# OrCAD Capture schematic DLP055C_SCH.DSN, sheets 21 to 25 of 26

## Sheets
21 P13 - DLPC Core Pwr: size A3
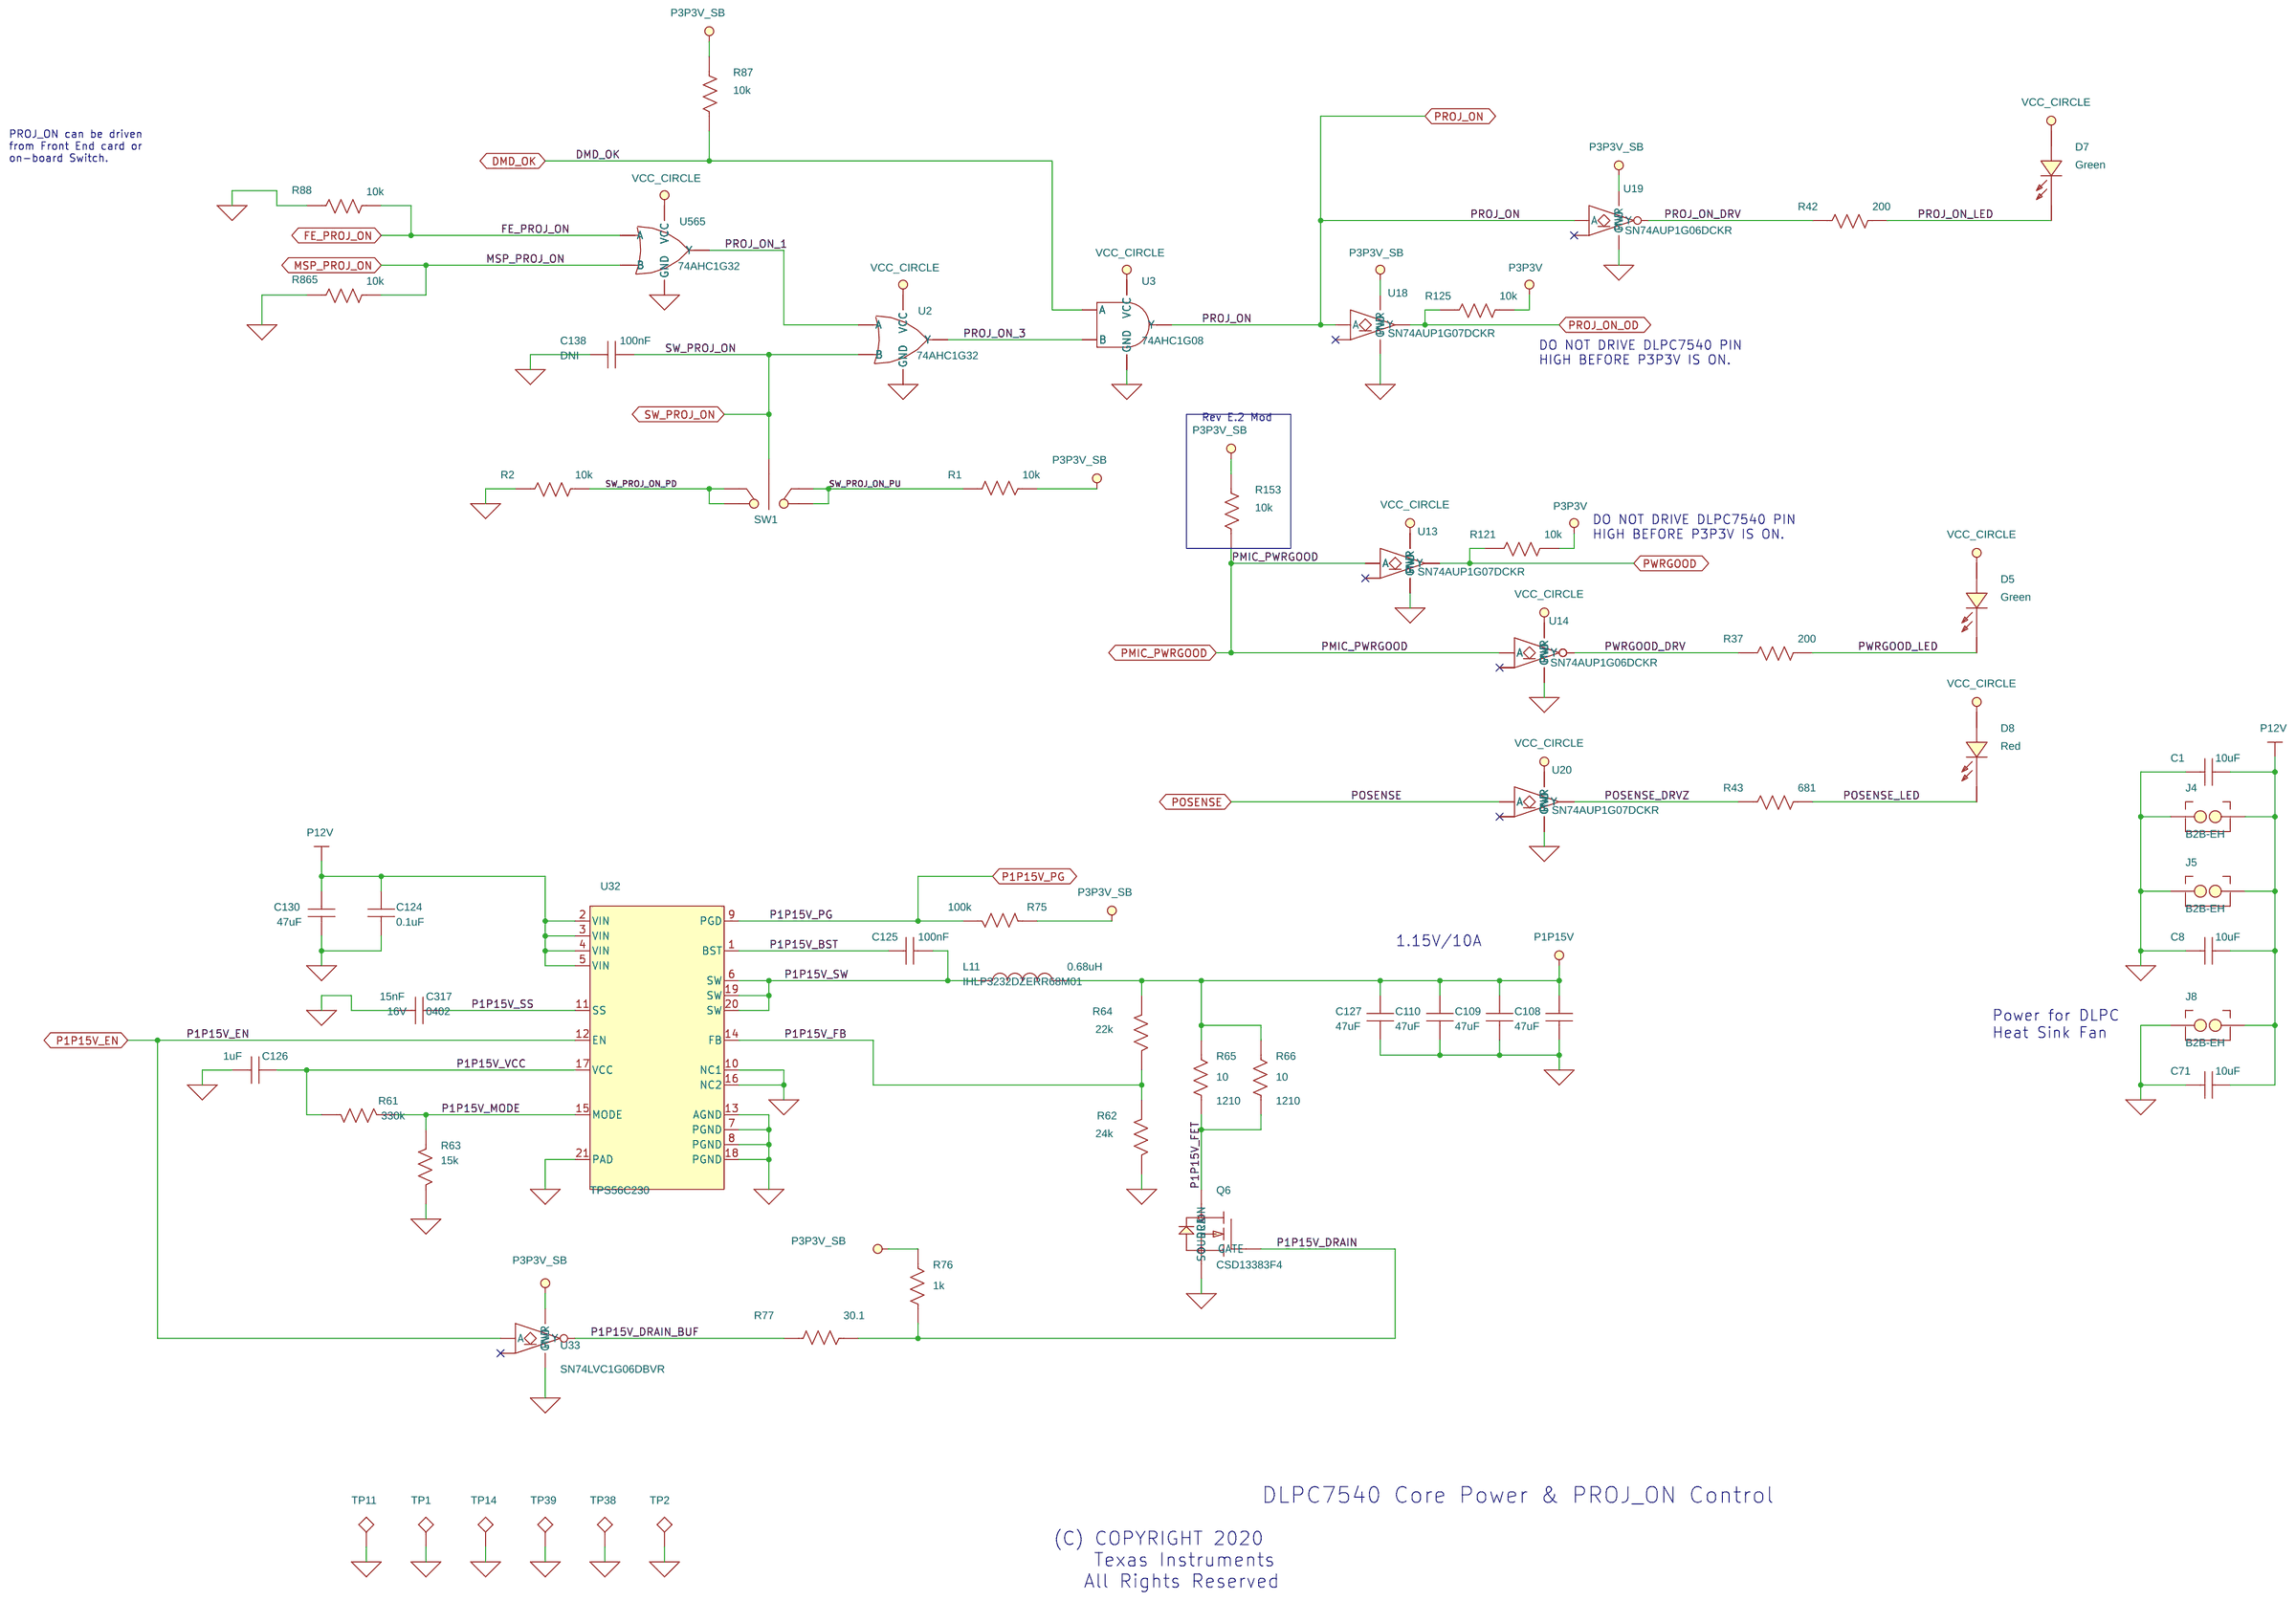
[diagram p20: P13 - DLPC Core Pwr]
22 P10 - DLPC PWR: size A3
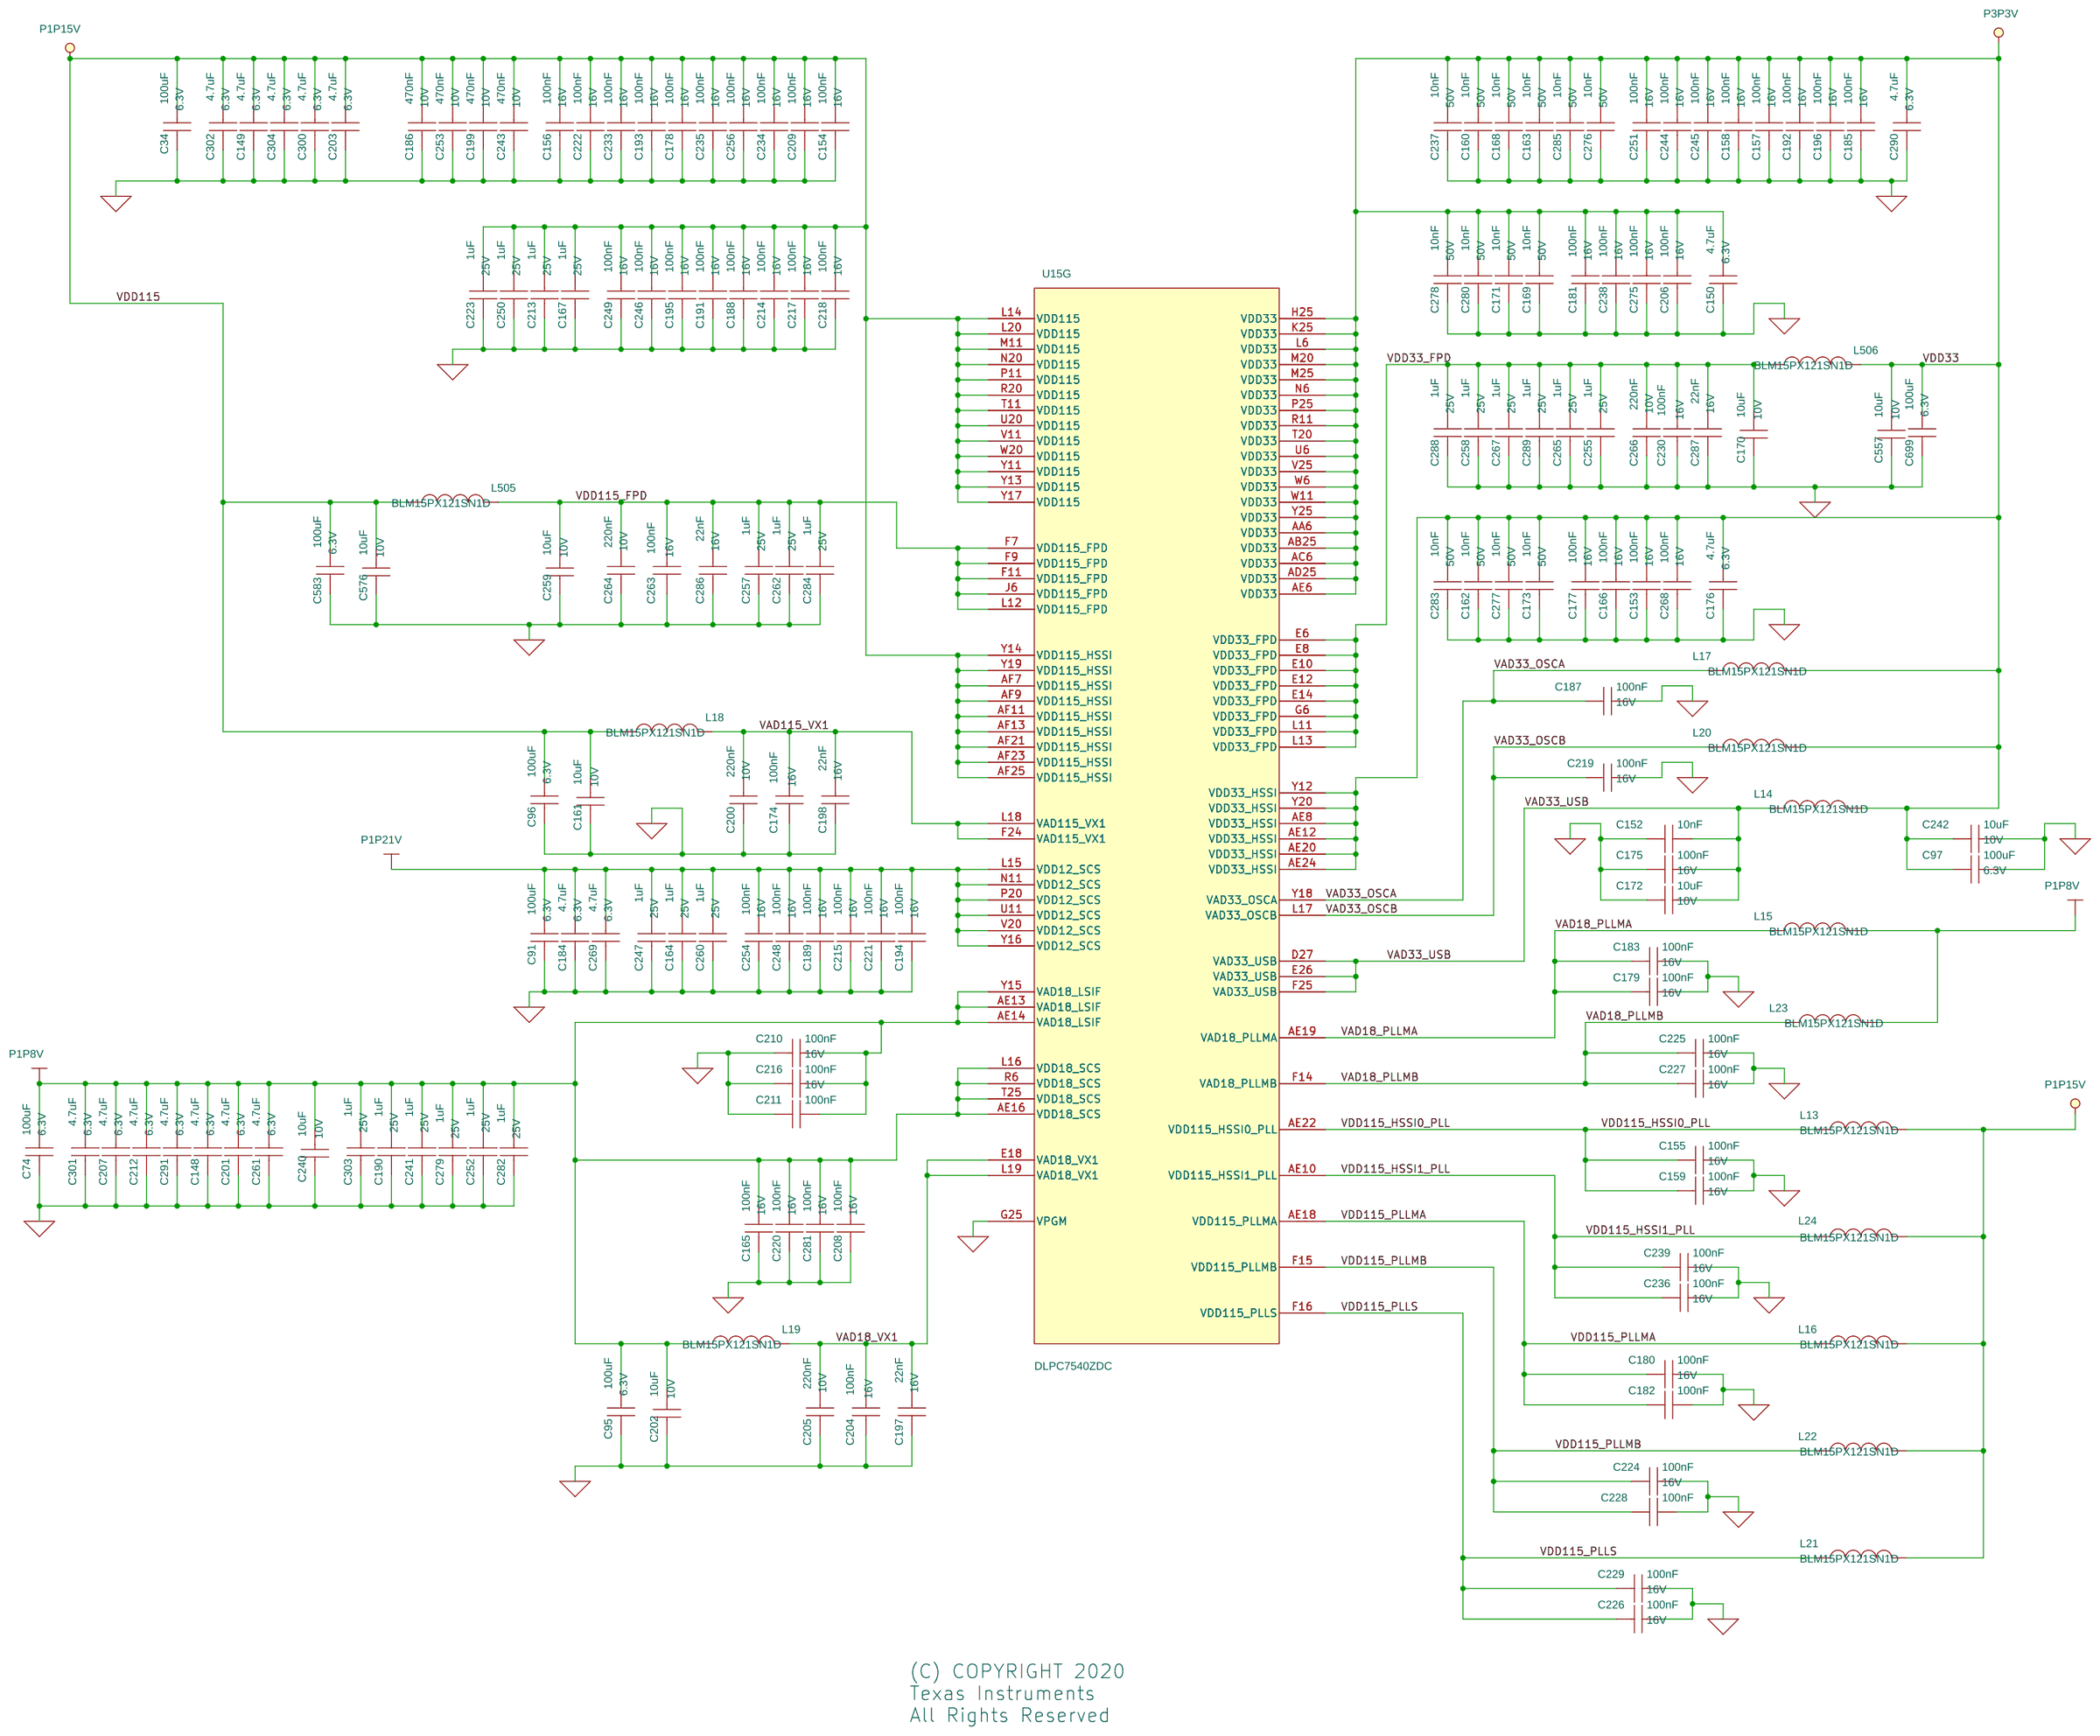
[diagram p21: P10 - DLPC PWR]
23 P11 - DLPC GND & NC: size A3
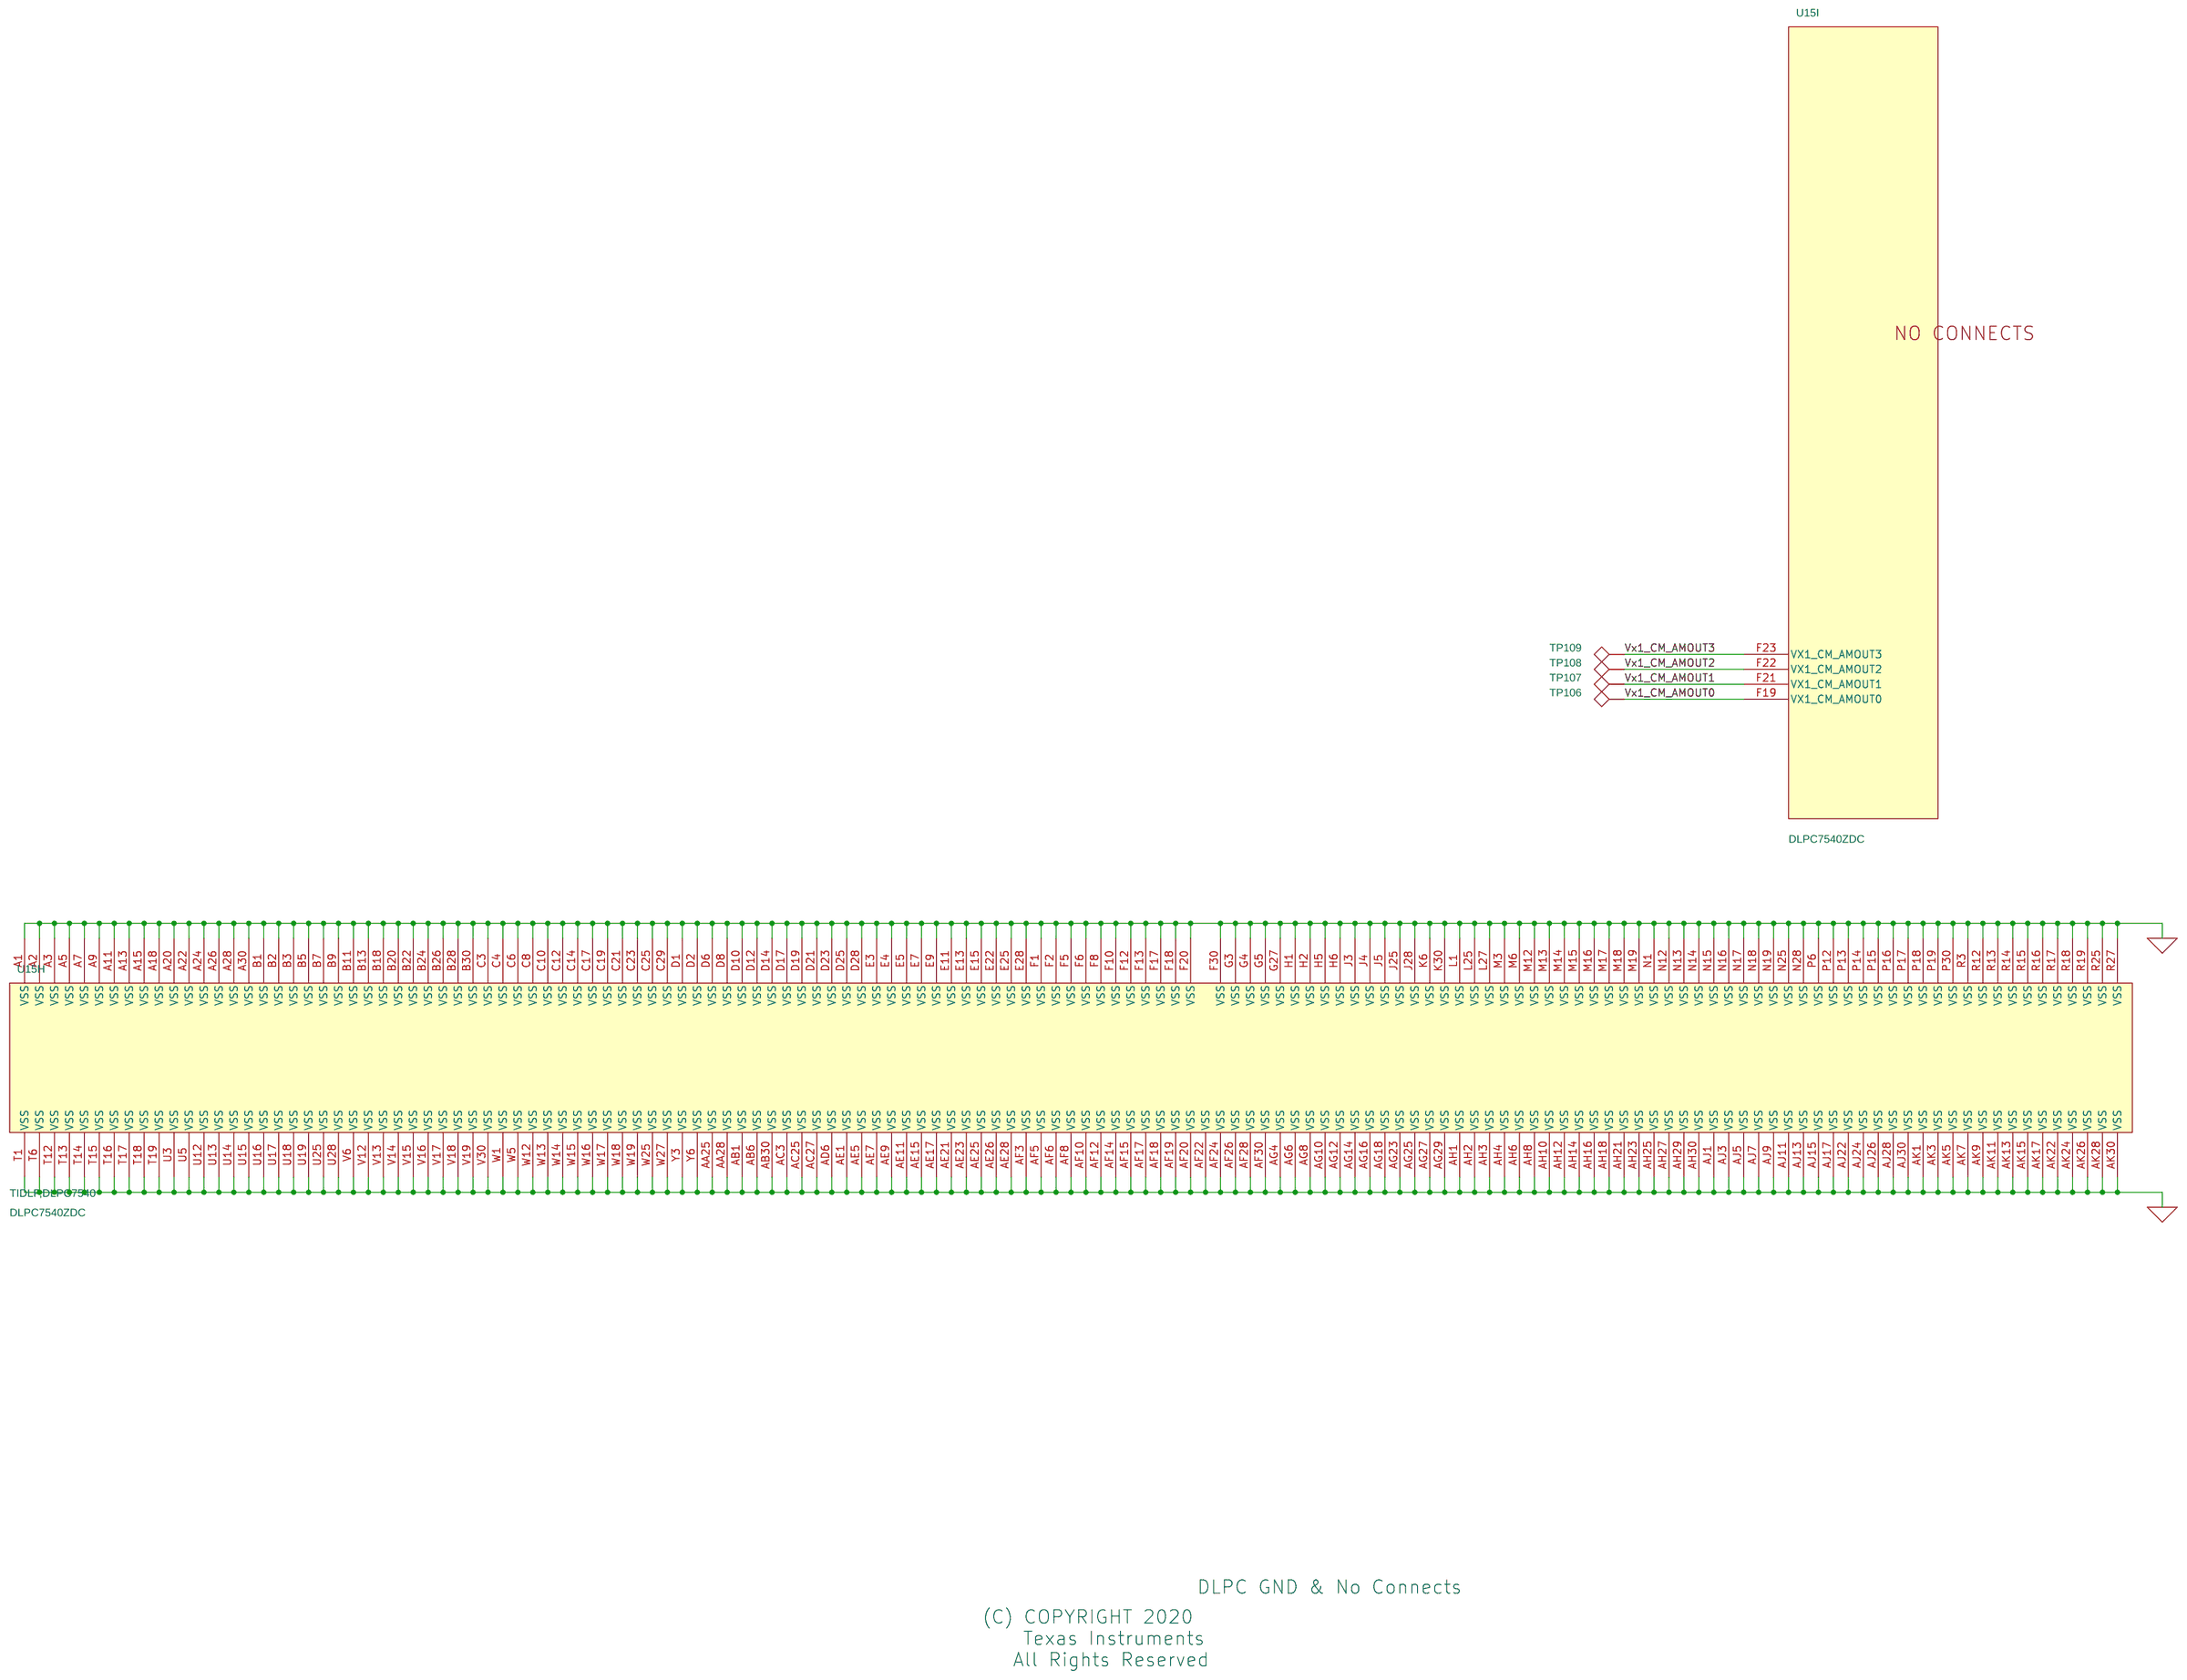
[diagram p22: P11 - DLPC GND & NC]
24 P26 - IMPORTANT NOTICE
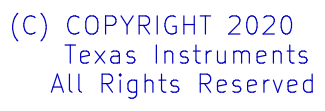
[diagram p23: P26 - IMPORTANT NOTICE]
25 P18 - DLPC SSI DRVR I/F: size A3
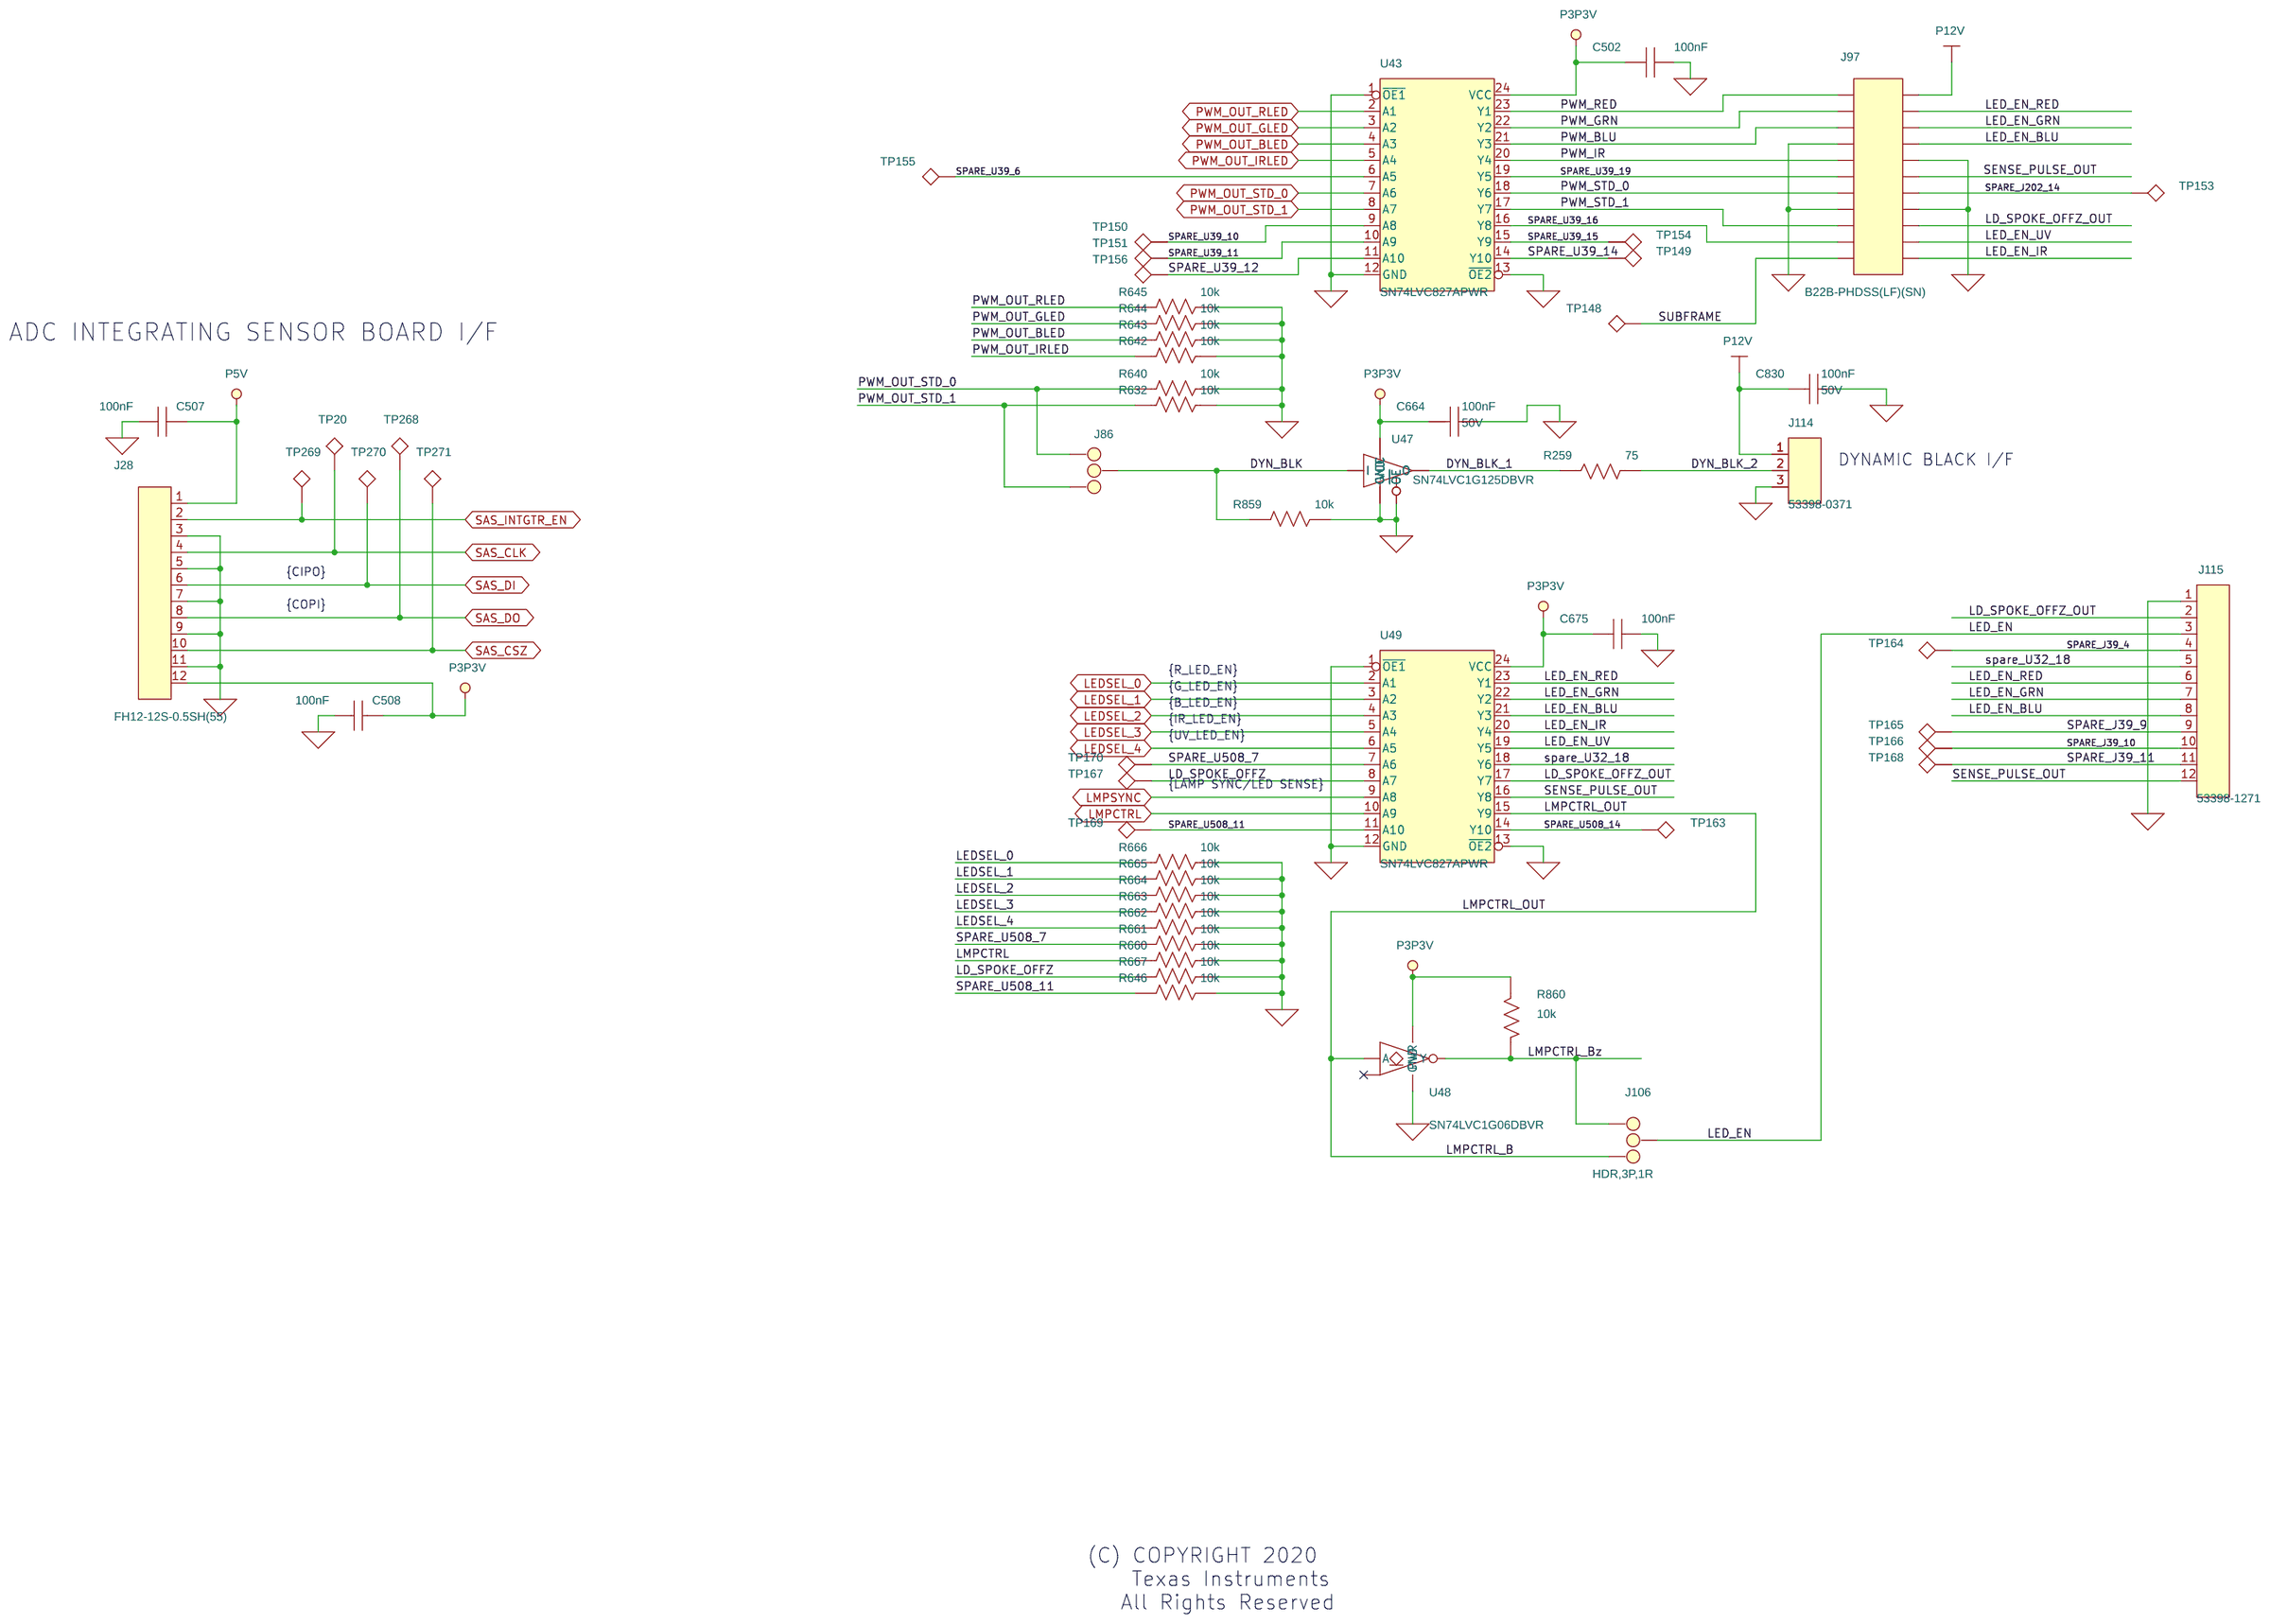
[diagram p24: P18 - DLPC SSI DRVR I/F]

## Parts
sheet P09 - DLPC GPIO
U15  TIDLP,DLPC7540  [DLPC7540_HBGA676_3131]  (sections A,B,C,D,E,F,G,H,I)
sheet P10 - DLPC PWR
C34  100uF  [1210]
C74  100uF  [1210]
C91  100uF  [1210]
C95  100uF  [1210]
C96  100uF  [1210]
C97  100uF  [1210]
C148  4.7uF  [0402]
C149  4.7uF  [0402]
C150  4.7uF  [0402]
C152  10nF  [0402]
C153  100nF  [0402]
C154  100nF  [0402]
C155  100nF  [0402]
C156  100nF  [0402]
C157  100nF  [0402]
C158  100nF  [0402]
C159  100nF  [0402]
C160  10nF  [0402]
C161  10uF  [0603]
C162  10nF  [0402]
C163  10nF  [0402]
C164  1uF  [0402]
C165  100nF  [0402]
C166  100nF  [0402]
C167  1uF  [0402]
C168  10nF  [0402]
C169  10nF  [0402]
C170  10uF  [0603]
C171  10nF  [0402]
C172  10uF  [0603]
C173  10nF  [0402]
C174  100nF  [0402]
C175  100nF  [0402]
C176  4.7uF  [0402]
C177  100nF  [0402]
C178  100nF  [0402]
C179  100nF  [0402]
C180  100nF  [0402]
C181  100nF  [0402]
C182  100nF  [0402]
C183  100nF  [0402]
C184  4.7uF  [0402]
C185  100nF  [0402]
C186  470nF  [0402]
C187  100nF  [0402]
C188  100nF  [0402]
C189  100nF  [0402]
C190  1uF  [0402]
C191  100nF  [0402]
C192  100nF  [0402]
C193  100nF  [0402]
C194  100nF  [0402]
C195  100nF  [0402]
C196  100nF  [0402]
C197  22nF  [0402]
C198  22nF  [0402]
C199  470nF  [0402]
C200  220nF  [0402]
C201  4.7uF  [0402]
C202  10uF  [0603]
C203  4.7uF  [0402]
C204  100nF  [0402]
C205  220nF  [0402]
C206  100nF  [0402]
C207  4.7uF  [0402]
C208  100nF  [0402]
C209  100nF  [0402]
C210  100nF  [0402]
C211  100nF  [0402]
C212  4.7uF  [0402]
C213  1uF  [0402]
C214  100nF  [0402]
C215  100nF  [0402]
C216  100nF  [0402]
C217  100nF  [0402]
C218  100nF  [0402]
C219  100nF  [0402]
C220  100nF  [0402]
C221  100nF  [0402]
C222  100nF  [0402]
C223  1uF  [0402]
C224  100nF  [0402]
C225  100nF  [0402]
C226  100nF  [0402]
C227  100nF  [0402]
C228  100nF  [0402]
C229  100nF  [0402]
C230  100nF  [0402]
C233  100nF  [0402]
C234  100nF  [0402]
C235  100nF  [0402]
C236  100nF  [0402]
C237  10nF  [0402]
C238  100nF  [0402]
C239  100nF  [0402]
C240  10uF  [0603]
C241  1uF  [0402]
C242  10uF  [0603]
C243  470nF  [0402]
C244  100nF  [0402]
C245  100nF  [0402]
C246  100nF  [0402]
C247  1uF  [0402]
C248  100nF  [0402]
C249  100nF  [0402]
C250  1uF  [0402]
C251  100nF  [0402]
C252  1uF  [0402]
C253  470nF  [0402]
C254  100nF  [0402]
C255  1uF  [0402]
C256  100nF  [0402]
C257  1uF  [0402]
C258  1uF  [0402]
C259  10uF  [0603]
C260  1uF  [0402]
C261  4.7uF  [0402]
C262  1uF  [0402]
C263  100nF  [0402]
C264  220nF  [0402]
C265  1uF  [0402]
C266  220nF  [0402]
C267  1uF  [0402]
C268  100nF  [0402]
C269  4.7uF  [0402]
C275  100nF  [0402]
C276  10nF  [0402]
C277  10nF  [0402]
C278  10nF  [0402]
C279  1uF  [0402]
C280  10nF  [0402]
C281  100nF  [0402]
C282  1uF  [0402]
C283  10nF  [0402]
C284  1uF  [0402]
C285  10nF  [0402]
C286  22nF  [0402]
C287  22nF  [0402]
C288  1uF  [0402]
C289  1uF  [0402]
C290  4.7uF  [0402]
C291  4.7uF  [0402]
C300  4.7uF  [0402]
C301  4.7uF  [0402]
C302  4.7uF  [0402]
C303  1uF  [0402]
C304  4.7uF  [0402]
C557  10uF  [0603]
C576  10uF  [0603]
C583  100uF  [1210]
C699  100uF  [1210]
L13  BLM15PX121SN1D  [0402]
L14  BLM15PX121SN1D  [0402]
L15  BLM15PX121SN1D  [0402]
L16  BLM15PX121SN1D  [0402]
L17  BLM15PX121SN1D  [0402]
L18  BLM15PX121SN1D  [0402]
L19  BLM15PX121SN1D  [0402]
L20  BLM15PX121SN1D  [0402]
L21  BLM15PX121SN1D  [0402]
L22  BLM15PX121SN1D  [0402]
L23  BLM15PX121SN1D  [0402]
L24  BLM15PX121SN1D  [0402]
L505  BLM15PX121SN1D  [0402]
L506  BLM15PX121SN1D  [0402]
sheet P11 - DLPC GND & NC
TP106  TP,28mil Drill,48mil Pad  [HTP-48RD28]
TP107  TP,28mil Drill,48mil Pad  [HTP-48RD28]
TP108  TP,28mil Drill,48mil Pad  [HTP-48RD28]
TP109  TP,28mil Drill,48mil Pad  [HTP-48RD28]
sheet P13 - DLPC Core Pwr
C1  10uF  [1210]
C8  10uF  [1210]
C71  10uF  [1210]
C108  47uF  [1206]
C109  47uF  [1206]
C110  47uF  [1206]
C124  0.1uF  [0805]
C125  100nF  [0402]
C126  1uF  [0402]
C127  47uF  [1206]
C130  47uF  [1206]
C138  100nF  [0402]
C317  15nF  [0402]
D5  Green  [LED-LTST-C190_LITEON]
D7  Green  [LED-LTST-C190_LITEON]
D8  Red  [LED-LTST-C190_LITEON]
J4  B2B-EH  [JST_B2B-EH]
J5  B2B-EH  [JST_B2B-EH]
J8  B2B-EH  [JST_B2B-EH]
L11  0.68uH  [IHLP3232DZER]
Q6  CSD13383F4  [3-PICOSTAR_3-XFDFN]
R1  10k  [0402]
R2  10k  [0402]
R37  200  [0402]
R42  200  [0402]
R43  681  [0402]
R61  330k  [0402]
R62  24k  [0201]
R63  15k  [0402]
R64  22k  [0402]
R65  10  [1210]
R66  10  [1210]
R75  100k  [0402]
R76  1k  [0402]
R77  30.1  [0402]
R87  10k  [0402]
R88  10k  [0402]
R121  10k  [0402]
R125  10k  [0402]
R153  10k  [0402]
R865  10k  [0402]
SW1  GT11MSCBE  [GT11MSCBE]
TP1  TP_BLK  [TP_Keystone_5011]
TP2  TP_BLK  [TP_Keystone_5011]
TP11  TP_BLK  [TP_Keystone_5011]
TP14  TP_BLK  [TP_Keystone_5011]
TP38  TP_BLK  [TP_Keystone_5011]
TP39  TP_BLK  [TP_Keystone_5011]
U2  74AHC1G32  [SOIC5-SOT-23_DBV-TI]
U3  74AHC1G08  [SOIC5-SOT-23_DBV-TI]
U13  SN74AUP1G07DCK  [U_5_DCK]
U14  SN74AUP1G06DCK  [U_5_DCK]
U18  SN74AUP1G07DCK  [U_5_DCK]
U19  SN74AUP1G06DCK  [U_5_DCK]
U20  SN74AUP1G07DCK  [U_5_DCK]
U32  TPS56C230  [20VQFN-HR_RJE]
U33  SN74LVC1G06DBVR  [SOIC5-SOT-23_DBV-TI]
U565  74AHC1G32  [SOIC5-SOT-23_DBV-TI]
sheet P18 - DLPC SSI DRVR I/F
C502  100nF  [0402]
C507  100nF  [0402]
C508  100nF  [0402]
C664  100nF  [0402]
C675  100nF  [0402]
C830  100nF  [0402]
J28  FH12-12S-0.5SH(55)  [CONN12-FH12_HRS]
J86  HDR,3P,1R  [HDR1X3]
J97  B22B-PHDSS(LF)(SN)  [CONN22-B22B-PHD_JST]
J106  HDR,3P,1R  [HDR1X3_2MM]
J114  53398-0371  [CONN3-53398-A_MOLEX]
J115  53398-1271  [CONN12-53398_MOLEX]
R259  75  [0402]
R632  10k  [0402]
R640  10k  [0402]
R642  10k  [0402]
R643  10k  [0402]
R644  10k  [0402]
R645  10k  [0402]
R646  10k  [0402]
R660  10k  [0402]
R661  10k  [0402]
R662  10k  [0402]
R663  10k  [0402]
R664  10k  [0402]
R665  10k  [0402]
R666  10k  [0402]
R667  10k  [0402]
R859  10k  [0402]
R860  10k  [0402]
TP20  TP_WHT  [TP_Keystone_5011]
TP148  TP_WHT  [TP_Keystone_5011]
TP149  TP_WHT  [TP_Keystone_5011]
TP150  TP_WHT  [TP_Keystone_5011]
TP151  TP_WHT  [TP_Keystone_5011]
TP153  TP_WHT  [TP_Keystone_5011]
TP154  TP_WHT  [TP_Keystone_5011]
TP155  TP_WHT  [TP_Keystone_5011]
TP156  TP_WHT  [TP_Keystone_5011]
TP163  TP_WHT  [TP_Keystone_5011]
TP164  TP_WHT  [TP_Keystone_5011]
TP165  TP_WHT  [TP_Keystone_5011]
TP166  TP_WHT  [TP_Keystone_5011]
TP167  TP_WHT  [TP_Keystone_5011]
TP168  TP_WHT  [TP_Keystone_5011]
TP169  TP_WHT  [TP_Keystone_5011]
TP170  TP_WHT  [TP_Keystone_5011]
TP268  TP_WHT  [TP_Keystone_5011]
TP269  TP_WHT  [TP_Keystone_5011]
TP270  TP_WHT  [TP_Keystone_5011]
TP271  TP_WHT  [TP_Keystone_5011]
U43  SN74LVC827APWR  [SOIC24-PW_TI]
U47  TSOP34838  [SOIC5-SOT-23_DBV-TI]
U48  SN74LVC1G06DBVR  [SOIC5-SOT-23_DBV-TI]
U49  SN74LVC827APWR  [SOIC24-PW_TI]

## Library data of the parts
U15 = TIDLP,DLPC7540: MFG: Texas Instruments; Part Number: DLPC7540ZDC
C34 C74 C91 C95 C96 = PAS,CAP,NP: DigiKey: 587-4313-1-ND; DigiReel: 587-4313-6-ND; Family: passive; Lead Style: SMT; MFG: Taiyo Yuden; Material: x5r; P/D_NUM: JMK325ABJ107MM-P; Part Number: JMK325ABJ107MM-P; Part Specific: CAP CER 100UF 6.3V 20% X5R 1210; Tolerance: 20%; VPC: 6.3V; Vendor: Taiyo Yuden
C97 = PAS,CAP,NP: DigiKey: 587-4313-1-ND; DigiReel: 587-4313-6-ND; Family: passive; Install: Y; Lead Style: SMT; MFG: Taiyo Yuden; Material: x5r; P/D_NUM: JMK325ABJ107MM-P; Part Number: JMK325ABJ107MM-P; Part Specific: CAP CER 100UF 6.3V 20% X5R 1210; TOLERANCE: 20%; Type: capacitor; VPC: 6.3V; Vendor: Taiyo Yuden
C148-C150 C176 C184 C201 C203 C207 C212 C261 C269 C290 C291 C300-C302 C304 = PAS,CAP,NP: ALT_SYMBOLS: 0402_1mm; DigiKey: 490-5915-1-ND; DigiReel: 490-5915-6-ND; Family: passive; Index PN: 1389; Lead Style: SMT; MFG: Murata; Material: x5r; P/D_NUM: GRM155R60J475ME47D; Part Number: GRM155R60J475ME47D; Part Specific: CAP CER 4.7UF 6.3V 20% X5R 0402; Tolerance: 20%; VPC: 6.3V; Vendor: Murata
C152 = PAS,CAP,NP: ALT_SYMBOLS: 0402_1mm; CCA: 39; DigiKey: 490-13295-1-ND; DigiReel: 490-13295-6-ND; Family: passive; Index PN: 1330; Install: Y; Lead Style: SMT; MFG: Murata; Material: x7r; P/D_NUM: GCM155R71H103KA55J; Part Number: GCM155R71H103KA55J; Part Specific: CAP CER 10000PF 50V 10% X7R 0402; TOLERANCE: 10%; Type: capacitor; VPC: 50V; Vendor: Murata
C153-C159 C165 C166 C174 C175 C177-C181 C183 C185 C188 C189 C191-C196 C204 C206 C208-C210 C214-C222 C224-C227 C229 C230 C233-C236 C238 C239 C244-C246 C248 C249 C251 C254 C256 C263 C268 C275 C281 = PAS,CAP,NP: ALT_SYMBOLS: 0402_1mm; DigiKey: 1276-1001-1-ND; Family: passive; Index PN: 681; Lead Style: SMT; MFG: Samsung; Material: x7r; P/D_NUM: CL05B104KO5NNNC; Part Number: CL05B104KO5NNNC; Part Specific: CAP CER .1UF 16V X7R 0402; Tolerance: 10%; VPC: 16V; Vendor: Samsung
C160 C162 C163 C168 C169 C171 C173 C237 C276-C278 C280 C283 C285 = PAS,CAP,NP: ALT_SYMBOLS: 0402_1mm; DigiKey: 490-13295-1-ND; DigiReel: 490-13295-6-ND; Family: passive; Index PN: 1330; Lead Style: SMT; MFG: Murata; Material: x7r; P/D_NUM: GCM155R71H103KA55J; Part Number: GCM155R71H103KA55J; Part Specific: CAP CER 10000PF 50V 10% X7R 0402; Tolerance: 10%; VPC: 50V; Vendor: Murata
C161 C170 C172 C202 C240 C259 = PAS,CAP,NP: DigiKey: 445-6853-1-ND; DigiReel: 445-6853-6-ND; Family: passive; Index PN: 1207; Install: Y; Lead Style: SMT; MFG: TDK; P/D_NUM: C1608X5R1A106M080AC; Part Number: C1608X5R1A106M080AC; Part Specific: CAP CER 10UF 10V 20% X5R 0603; TOLERANCE: 20%; Type: capacitor; VPC: 10V; Vendor: TDK
C164 C167 C190 C213 C223 C241 C247 C250 C252 C255 C257 C258 C260 C262 C265 C267 C279 C282 C284 C288 C289 C303 = PAS,CAP,NP: ALT_SYMBOLS: 0402_1mm; DigiKey: 490-12263-1-ND; DigiReel: 490-12263-6-ND; Family: passive; Lead Style: SMT; MFG: Murata; P/D_NUM: GRM155R61E105MA12D; Part Number: GRM155R61E105MA12D; Part Specific: CAP CER 1UF 25V 10% X5R 0402; Tolerance: 10%; VPC: 25V; Vendor: Samsung; Voltage: 25V
C182 C187 C211 C228 = PAS,CAP,NP: ALT_SYMBOLS: 0402_1mm; CCA: 39; DigiKey: 1276-1001-1-ND; Family: passive; Index PN: 681; Install: Y; Lead Style: SMT; MFG: Samsung; Material: x7r; P/D_NUM: CL05B104KO5NNNC; Part Number: CL05B104KO5NNNC; Part Specific: CAP CER .1UF 16V X7R 0402; TOLERANCE: 10%; Type: capacitor; VPC: 16V; Vendor: Samsung
C186 C199 C243 C253 = PAS,CAP,NP: ALT_SYMBOLS: 0402_1mm; DigiKey: 587-1455-1-ND; DigiReel: 587-1455-6-ND; Family: passive; Index PN: 1390; Lead Style: SMT; MFG: Taiyo Yuden; Material: x5r; P/D_NUM: LMK105BJ474KV-F; Part Number: LMK105BJ474KV-F; Part Specific: CAP CER 0.47UF 10V 10% X5R 0402; Tolerance: 10%; VPC: 10V; Vendor: Taiyo Yuden
C197 C198 C286 C287 = PAS,CAP,NP: ALT_SYMBOLS: 0402_1mm; DigiKey: 587-1224-1-ND; DigiReel: 587-1224-6-ND; Family: passive; Index PN: 1116; Lead Style: SMT; MFG: Taiyo Yuden; Material: x7r; P/D_NUM: EMK105B7223KV-F; Part Number: EMK105B7223KV-F; Part Specific: CAP CER 0.022UF 16V 10% X7R 0402; Tolerance: 10%; VPC: 16V; Vendor: Taiyo Yuden
C200 C205 C264 C266 = PAS,CAP,NP: ALT_SYMBOLS: 0402_1mm; DigiKey: 587-1228-1-ND; Family: passive; Index PN: 1282; Lead Style: SMT; MFG: Taiyo Yuden; Material: x5r; P/D_NUM: LMK105BJ224KV-F; Part Number: LMK105BJ224KV-F; Part Specific: CAP CER 0.22UF 10V 10% X5R 0402; Tolerance: 10%; VPC: 10V; Vendor: Taiyo Yuden
C242 = PAS,CAP,NP: DigiKey: 445-6853-1-ND; DigiReel: 445-6853-6-ND; Family: passive; Index PN: 1207; Lead Style: SMT; MFG: TDK; P/D_NUM: C1608X5R1A106M080AC; Part Number: C1608X5R1A106M080AC; Part Specific: CAP CER 10UF 10V 20% X5R 0603; Tolerance: 20%; VPC: 10V; Vendor: TDK
C557 C576 = PAS,CAP,NP: CCA: 34; DigiKey: 445-6853-1-ND; Family: passive; Index PN: 1207; Install: Y; Lead Style: SMT; MFG: TDK; P/D_NUM: C1608X5R1A106M080AC; Part Number: C1608X5R1A106M080AC; Part Specific: CAP CER 10UF 10V 20% X5R 0603; TOLERANCE: 20%; Type: capacitor; VPC: 10V; Vendor: TDK
C583 C699 = PAS,CAP,NP: DigiKey: 490-10530-1-ND; Family: passive; Index PN: 1636; Lead Style: SMT; MFG: Murata; Material: x7s; P/D_NUM: GRM32EC70J107ME15L; Part Number: GRM32EC70J107ME15L; Part Specific: CAP CER 100UF 6.3V X7S 1210; Tolerance: 20%; VPC: 6.3V; Vendor: Murata
L13-L24 L505 L506 = PAS,INDUCTOR: ALT_SYMBOLS: 0402_1mm; DigiKey: 490-9656-1-ND; Family: passive; Index PN: 1670; Lead Style: SMT; MFG: Murata; Part Specific: FERRITE BEAD 120 OHM 0402 2A 50Ohm DC; Type: ferrite bead; VPC: 2000mA; Vendor: Murata
TP106-TP109 = EM,TERM,TESTPOINT: DigiKey: ---; Family: board feature; Index PN: 1498; Install: DNI; Lead Style: TH; MFG: -- NOT A PART --; Part Specific: HOLE PLATED 48mil pad 28mil drill; Type: hole,plated; Vendor: -- NOT A PART --
C1 C8 C71 = PAS,CAP,NP: DigiKey: 1276-3388-1-ND; DigiReel: 1276-3388-6-ND; Family: passive; Lead Style: SMT; MFG: Samsung; Material: x7r; P/D_NUM: CL32B106KBJNNWE; Part Number: CL32B106KBJNNWE; Part Specific: CAP CER 10UF 50V 10% X7R 1210; Tolerance: 10%; VPC: 50V; Vendor: Samsung; Voltage: 50V
C108-C110 C127 = PAS,CAP,NP: DigiKey: 1276-1167-1-ND; DigiReel: 1276-1167-6-ND; Family: passive; Lead Style: SMT; MFG: Samsung; Material: x5r; P/D_NUM: CL31A476MQHNNNE; Part Number: CL31A476MQHNNNE; Part Specific: CAP CER 47UF 6.3V 20% X5R 1206; Tolerance: 20%; VPC: 6.3V; Vendor: TDK; Voltage: 6.3V
C124 = PAS,CAP,NP: ALT_SYMBOLS: 0402_1mm; DigiKey: 478-1395-1-ND; DigiReel: 478-1395-6-ND; Family: passive; Lead Style: SMT; MFG: AVX; Material: x7r; P/D_NUM: 08055C104KAT2A; Part Number: 08055C104KAT2A; Part Specific: CAP CER 0.1UF 50V 10% X7R 0805; Tolerance: 10%; VPC: 50V; Vendor: AVX; Voltage: 50V
C125 = PAS,CAP,NP: ALT_SYMBOLS: 0402_1mm; DigiKey: 1276-1001-1-ND; Family: passive; Index PN: 681; Install: Y; Lead Style: SMT; MFG: Samsung; Material: x7r; P/D_NUM: CL05B104KO5NNNC; Part Number: CL05B104KO5NNNC; Part Specific: CAP CER .1UF 16V X7R 0402; TOLERANCE: 10%; Type: capacitor; VENDOR: Samsung; VPC: 16V
C126 = PAS,CAP,NP: DigiKey: 490-12263-1-ND; DigiReel: 490-12263-6-ND; Family: passive; Install: Y; Lead Style: SMT; MFG: Murata; Material: x5r; P/D_NUM: GRM155R61E105MA12D; Part Number: GRM155R61E105MA12D; Part Specific: CAP CER 1UF 25V 10% X5R 0402; TOLERANCE: 10%; Type: capacitor; VPC: 25V; Vendor: Murata; Voltage: 25V
C130 = PAS,CAP,NP: DigiKey: 445-8047-1-ND; DigiReel: 445-8047-6-ND; Family: passive; Lead Style: SMT; MFG: TDK; Material: x5r; P/D_NUM: C3216X5R1E476M160AC; Part Number: C3216X5R1E476M160AC; Part Specific: CAP CER 47UF 25V 20% X5R 1206; Tolerance: 20%; VPC: 25V; Vendor: TDK; Voltage: 25V
C138 = PAS,CAP,NP: ALT_SYMBOLS: 0402_1mm; DigiKey: 1276-1001-1-ND; Family: passive; Index PN: 681; Install: DNI; Lead Style: SMT; MFG: Samsung; Material: x7r; P/D_NUM: CL05B104KO5NNNC; Part Number: CL05B104KO5NNNC; Part Specific: CAP CER .1UF 16V X7R 0402; TOLERANCE: 10%; Type: capacitor; VENDOR: Samsung; VPC: 16V
C317 = PAS,CAP,NP: ALT_SYMBOLS: 0402_1mm; CCA: 34; DigiKey: 1276-1524-1-ND; Family: passive; Index PN: 1692; Install: Y; Lead Style: SMT; MFG: Samsung; Material: x7r; P/D_NUM: EMK105B7153KV-F; Part Number: EMK105B7153KV-F; Part Specific: CAP CER 0.015UF 16V X7R 0402; TOLERANCE: 10%; Type: capacitor; VPC: 16V; Vendor: Samsung
D5 D7 = PAS,DIODE,LED,ALT: DigiKey: 160-1183-1-ND; DigiReel: 160-1183-6-ND; Family: passive; Index PN: 1451; Install: Y; Lead Style: SMT; MFG: Liteon; P/D_NUM: LTST-C190GKT; Part Number: LTST-C190GKT; Part Specific: LED GREEN CLEAR 0603 SMD; Type: diode,led; Vendor: Liteon
D8 = PAS,DIODE,LED,ALT: DigiKey: 160-1447-1-ND; Family: passive; Index PN: 1452; Install: Y; Lead Style: SMT; MFG: Liteon; P/D_NUM: LTST-C191KRKT; Part Number: LTST-C191KRKT; Part Specific: LED RED CLEAR 0603 SMD; Type: diode,led; Vendor: Liteon
J4 J5 J8 = EM,HDR,2P,1R,1x,B2B_EH,inline: DigiKey: 455-1611-ND; Family: electro/mechanical; Index PN: 1297; Lead Style: TH; MFG: JST; P/D_NUM: B2B-EH-A(LF)(SN); Part Number: B2B-EH-A(LF)(SN); Part Specific: CONN HEADER EH TOP 2POS 2.5MM; Pin Cnt: 3; Pin Spacing: 2.5MM; Row Cnt: 1; Type: header; Vendor: JST
L11 = PAS,INDUCTOR: DigiKey: 541-1381-1-ND; DigiReel: 541-1381-6-ND; Family: passive; Lead Style: SMT; MFG: Vishay/Dale; P/D_NUM: IHLP3232DZERR68M01; Part Number: IHLP3232DZERR68M01; Part Specific: INDUCTOR 680NH 20% 21A 3.67 MOHM SMD; Tolerance: 20%; Type: inductor; VPC: 21A; Vendor: Vishay/Dale
Q6 = ANA,MOSFET,N-CH,E,3PICOSTAR_0: DigiKey: 296-39991-1-ND; DigiReel: 296-39991-6-ND; Family: analog; Index PN: 1715; MFG: Texas Instruments; Part Specific: MOSFET N-CH 12V 3PICOSTAR; Type: mosfet; Vendor: Texas Instruments
R1 = PAS,R,large: ALT_SYMBOLS: 0402_1mm; DigiKey: 311-10.0KLRCT-ND; DigiReel: 311-10.0KLRDKR-ND; Family: passive; Index PN: 680; Install: Y; Lead Style: SMT; MFG: Yageo; Material: chip; P/D_NUM: RC0402FR-0710KL; Part Number: RC0402FR-0710KL; Part Specific: RES 10K OHM 1% 1/16W 0402 SMD; Power: 1/16W; TOLERANCE: 1%; Type: resistor; VPC: 1/16W; Vendor: Yageo
R2 R87 R88 R121 R125 R153 R865 = PAS,R,large: ALT_SYMBOLS: 0402_1mm; DigiKey: 311-10.0KLRCT-ND; DigiReel: 311-10.0KLRDKR-ND; Family: passive; Index PN: 680; Lead Style: SMT; MFG: Yageo; Material: chip; P/D_NUM: RC0402FR-0710KL; Part Number: RC0402FR-0710KL; Part Specific: RES 10K OHM 1% 1/16W 0402 SMD; Power: 1/16W; TOLERANCE: 1%; Type: resistor; VENDOR: Yageo; VPC: 1/16W
R37 R42 = PAS,R,large: DigiKey: P200LCT-ND; DigiReel: P200LDKR-ND; Family: passive; ICA_MFR_NAME: PANASONIC; ICA_PARTNUM: $$1785048$$ERJ-3GSYJ102; Index PN: 1735; Install: Y; Lead Style: SMT; MFG: Panasonic; Material: chip; P/D_NUM: ERJ-2RKF2000X; Part Number: ERJ-2RKF2000X; Part Specific: RES 200 OHM 1% 1/10W 0402 SMD; TOLERANCE: 1%; Type: resistor; VPC: 1/16W; Vendor: Panasonic
R43 = PAS,R,large: ALT_SYMBOLS: 0402_1mm; CCA: 95; DigiKey: P681LCT-ND; Family: passive; ICA_MFR_NAME: PANASONIC; ICA_PARTNUM: $$1785048$$ERJ-3GSYJ102; Index PN: 1119; Install: Y; Lead Style: SMT; MFG: Panasonic; Material: chip; P/D_NUM: ERJ-2RKF6810X; Part Number: ERJ-2RKF6810X; Part Specific: RES 681 OHM 1/10W 1% 0402 SMD; TOLERANCE: 1%; Type: resistor; VPC: 1/10W; Vendor: Panasonic
R61 = PAS,R,large: ALT_SYMBOLS: 0402_1mm; DigiKey: P330KLCT-ND; DigiReel: P330KLDKR-ND; Family: passive; Install: Y; Lead Style: SMT; MFG: Panasonic; Material: chip; P/D_NUM: ERJ-2RKF3303X; Part Number: ERJ-2RKF3303X; Part Specific: RES 330K OHM 1% 1/10W 0402 SMD; Tolerance: 1%; Type: resistor; VPC: 1/10W; Vendor: Panasonic
R62 = PAS,R,large: DigiKey: P122858CT-ND; DigiReel: P122858DKR-ND; Family: passive; Install: Y; Lead Style: SMT; MFG: Panasonic; Material: chip; P/D_NUM: ERJ-1GNF2402C; Part Number: ERJ-1GNF2402C; Part Specific: RES 24K OHM 1% 1/20W 0201 SMD; Tolerance: 1%; Type: resistor; VPC: 1/20W; Vendor: Panasonic
R63 = PAS,R,large: ALT_SYMBOLS: 0402_1mm; DigiKey: P15.0KLCT-ND; DigiReel: P15.0KLDKR-ND; Family: passive; Install: Y; Lead Style: SMT; MFG: Panasonic; Material: chip; P/D_NUM: ERJ-2RKF1502X; Part Number: ERJ-2RKF1502X; Part Specific: RES 15K OHM 1% 1/10W 0402 SMD; Tolerance: 1%; Type: resistor; VPC: 1/10W; Vendor: Panasonic
R64 = PAS,R,large: ALT_SYMBOLS: 0402_1mm; DigiKey: YAG4356CT-ND; DigiReel: YAG4356DKR-ND; Family: passive; Index PN: 1686; Install: Y; Lead Style: SMT; MFG: Yageo; Material: chip; P/D_NUM: RT0402BRE0722KL; Part Number: RT0402BRE0722KL; Part Specific: RES 22K OHM 0.1% 1/16W 0402 SMD; Tolerance: 0.1%; Type: resistor; VPC: 1/16W; Vendor: Yageo
R65 R66 = PAS,R,large: DigiKey: P10VCT-ND; DigiReel: P10VDKR-ND; Family: passive; Index PN: 403; MFG: Panasonic; Material: chip; P/D_NUM: ERJ-14YJ100U; Part Number: ERJ-14YJ100U; Part Specific: RES 10 OHM 5% 1/2W 1210 SMD; Power: 1/4W; TOLERANCE: 5%; Type: resistor; VENDOR: Panasonic; VPC: 1/2W
R75 = PAS,R,large: ALT_SYMBOLS: 0402_1mm; DigiKey: 311-100KLRCT-ND; DigiReel: 311-100KLRDKR-ND; Family: passive; Lead Style: SMT; MFG: Yageo; Material: chip; P/D_NUM: RC0402FR-07100KL; Part Number: RC0402FR-07100KL; Part Specific: RES 100K OHM 1/10W 1% 0402 SMD; Power: 1/16W; Tolerance: 1%; Type: resistor; VPC: 1/16W; Vendor: Yageo
R76 = PAS,R,large: ALT_SYMBOLS: 0402_1mm; DigiKey: P1.00KLCT-ND; DigiReel: P1.00KLDKR-ND; Family: passive; Index PN: 684; Lead Style: SMT; MFG: Panasonic; Material: chip; P/D_NUM: ERJ-2RKF1001X; Part Number: ERJ-2RKF1001X; Part Specific: RES 1.00K OHM 1/10W 1% 0402 SMD; Power: 1/16W; TOLERANCE: 1%; Type: resistor; VENDOR: Panasonic; VPC: 1/16W
R77 = PAS,R,large: Resistor; ALT_SYMBOLS: 0402_1mm; CCA: 91; DigiKey: YAG3111CT-ND; Family: passive; ICA_MFR_NAME: PANASONIC; ICA_PARTNUM: $$1785048$$ERJ-3GSYJ102; Index PN: 976; Install: Y; Lead Style: SMT; MFG: Yageo; Material: chip; P/D_NUM: RC0402FR-0730R1L; Part Number: RC0402FR-0730R1L; Part Specific: RES 30.1 OHM 1/16W 1% 0402 SMD; Power: 1/16W; TOLERANCE: 1%; Type: resistor; VPC: 1/16W; Vendor: Yageo
SW1 = EM,SW,SPDT,GT11,1x: DigiKey: CKN1784CT-ND; DigiReel: CKN1784DKR-ND; Family: electro/mechanical; Index PN: 1035; Install: Y; Lead Style: SMT; MFG: C&K; Part Specific: SWITCH TOGGLE SPDT ULTRAMINI SMD; Type: switch; Vendor: C&K
TP1 TP2 TP11 TP14 TP38 TP39 = EM,TERM,TESTPOINT: DigiKey: 36-5011-ND; Family: electro/mechanical; Index PN: 1161; Install: Y; Lead Style: TH; MFG: Keystone; P/D_NUM: 5011; Part Number: 5011; Part Specific: TEST POINT PC MULTI PURPOSE BLK .063inD hole; Type: terminal; Vendor: Keystone
U2 U565 = LOG,OR,Tiny_Logic,small: DigiKey: 296-1093-1-ND; DigiReel: 296-1093-6-ND; Family: logic; Index PN: 163; MFG: Texas Instruments; P/D_NUM: SN74AHC1G32DBVR; Part Number: SN74AHC1G32DBVR; Part Specific: IC GATE OR 1CH 2-INP SOT23-5; Temp: C; Type: or; Vendor: Texas Instruments
U3 = LOG,AND,Tiny_Logic,Small: DigiKey: 296-1091-1-ND; Index PN: 162; MFG: Texas Instruments; P/D_NUM: SN74AHC1G08DBVR; Part Number: SN74AHC1G08DBVR; Part Specific: IC SGL 2IN POS-AND GATE SOT23-5; Temp: C; Type: and; Vendor: Texas Instruments
U13 = TMP_21: DigiKey: 296-18256-1-ND; Family: logic; Index PN: 1027; Lead Style: SMT; MFG: Texas Instruments; P/D_NUM: SN74AUP1G07DCKR; Part Number: SN74AUP1G07DCKR; Part Specific: IC BUFF/DVR LOW PWR N-INV SC705  open drain; Type: buffer
U14 = TMP_22: DigiKey: 296-17562-1-ND; DigiReel: 296-17562-6-ND; Family: logic; Index PN: 1026; Lead Style: SMT; MFG: Texas Instruments; P/D_NUM: SN74AUP1G06DCKR; Part Number: SN74AUP1G06DCKR; Part Specific: IC INVERTER SINGLE 1INPUT SC705  open drain; Type: buffer
U18 = TMP_20: DigiKey: 296-18256-1-ND; Family: logic; Index PN: 1027; Lead Style: SMT; MFG: Texas Instruments; P/D_NUM: SN74AUP1G07DCKR; Part Number: SN74AUP1G07DCKR; Part Specific: IC BUFF/DVR LOW PWR N-INV SC705  open drain; Type: buffer
U19 = TMP_19: DigiKey: 296-17562-1-ND; DigiReel: 296-17562-6-ND; Family: logic; Index PN: 1026; Lead Style: SMT; MFG: Texas Instruments; P/D_NUM: SN74AUP1G06DCKR; Part Number: SN74AUP1G06DCKR; Part Specific: IC INVERTER SINGLE 1INPUT SC705  open drain; Type: buffer
U20 = TMP_23: DigiKey: 296-18256-1-ND; Family: logic; Index PN: 1027; Lead Style: SMT; MFG: Texas Instruments; P/D_NUM: SN74AUP1G07DCKR; Part Number: SN74AUP1G07DCKR; Part Specific: IC BUFF/DVR LOW PWR N-INV SC705  open drain; Type: buffer
U32 = PWR,REG,TPS56C230,1X: DigiKey: 296-TPS56C230RJERCT-ND; DigiReel: 296-TPS56C230RJERDKR-ND; Family: power; Lead Style: SMT; MFG: Texas Instruments; P/D_NUM: TPS56C230RJER; Part Number: TPS56C230RJER; Part Specific: IC BUCK SYNC ADJ 12A 20VQFN; Type: regulator; Vendor: Texas Instruments
U33 = TMP_24: DigiKey: 296-8483-1-ND; Family: logic; Index PN: 1489; Lead Style: SMT; MFG: Texas Instruments; Part Specific: IC INVERTER SGL 1INPUT Open Drain; Type: inverter
C502 C507 C508 C675 = PAS,CAP,NP: ALT_SYMBOLS: 0402_1mm; CCA: 34; DigiKey: 587-3499-1-ND; Family: passive; Index PN: 1280; Install: Y; Lead Style: SMT; MFG: Taiyo Yuden; Material: x5r; P/D_NUM: UMK105BJ104KV-F; Part Number: UMK105BJ104KV-F; Part Specific: CAP CER 0.1UF 50V 10% X5R 0402; TOLERANCE: 10%; Type: capacitor; VPC: 50V; Vendor: Taiyo Yuden
C664 C830 = PAS,CAP,NP: Capacitor; ALT_SYMBOLS: 0402_1mm; CCA: 34; DigiKey: 587-3499-1-ND; Digikey Part Number: DIGI 399-3520-1-ND; Family: passive; Index PN: 1280; Install: Y; Lead Style: SMT; MFG: Taiyo Yuden; Material: x5r; P/D_NUM: UMK105BJ104KV-F; Part Number: UMK105BJ104KV-F; Part Specific: CAP CER 0.1UF 50V 10% X5R 0402; RATING: <RATING>; SOURCE: DIGI 399-3520-1-ND; TOLERANCE: 10%; Type: capacitor; VPC: 50V; Vendor: Taiyo Yuden
J28 = EM,HDR,12P,1R: DigiKey: HFJ112CT-ND; Family: electro/mechanical; Index PN: 1461; Lead Style: SMT; MFG: Hirose; Part Specific: CONN FFC BOTTOM 12POS 0.50MM R/A; Pin Cnt: 12; Row Cnt: 1; Type: connector; Vendor: Hirose
J86 = EM,JMP,3P,1R,1X,ALT: DigiKey: 952-2263-ND; Index PN: 20; Lead Style: TH; MFG: Harwin; P/D_NUM: M20-9990345; Part Number: M20-9990345; Part Specific: 3 Positions Header  Unshrouded  Breakaway Connector 0.100in (2.54mm) Through Hole Gold; Pin Cnt: 3; Pin Spacing: 100mil; Row Cnt: 1; Type: header; Vendor: Harwin
J97 = EM,HDR,22P,2R: CCA: 26; DigiKey: 455-1768-ND; Family: electro/mechanical; Index PN: 1580; Install: Y; Lead Style: TH; MFG: JST; Part Specific: 22 Positions Header Connector 0.079in (2.00mm) Through Hole Tin; Type: header; Vendor: JST
J106 = EM,JMP,3P,1R,1X,ALT: DigiKey: 952-1312-ND; Index PN: 1525; Lead Style: TH; MFG: Harwin; P/D_NUM: M22-2510305; Part Number: M22-2510305; Part Specific: CONN HEADER 2MM VERT AU 3POS; Pin Cnt: 3; Pin Spacing: 2mm; Row Cnt: 1; Type: header; Vendor: Harwin
J114 = EM,HDR,3P,1R: DigiKey: WM7607CT-ND; Family: electro/mechanical; Index PN: 1522; Lead Style: SMT; MFG: Molex; Part Specific: CONN HEADER 3POS 1.25MM VERT SMD; Pin Cnt: 3; Pin Spacing: 1.25mm; Row Cnt: 1; Type: connector; Vendor: Molex
J115 = EM,HDR,12P,1R: DigiKey: WM7616CT-ND; Family: electro/mechanical; Index PN: 1579; Lead Style: SMT; MFG: Molex; Part Specific: 12 Positions Header Connector 0.049in (1.25mm) Surface Mount Tin; Pin Cnt: 12; Pin Spacing: 1.25mm; Row Cnt: 1; Type: connector; Vendor: Molex
R259 = PAS,R,large: Resistor; ALT_SYMBOLS: 0402_1mm; CCA: 74; DigiKey: 311-75.0LRCT-ND; Digikey Part Number: DIGI P6.49KLCT-ND; Family: passive; ICA_MFR_NAME: PANASONIC; ICA_PARTNUM: $$1785048$$ERJ-3GSYJ102; Index PN: 1166; Install: Y; Lead Style: SMT; MFG: Yageo; Material: chip; P/D_NUM: RC0402FR-0775RL; Part Number: RC0402FR-0775RL; Part Specific: RES SMD 75 OHM 1% 1/16W 0402; SOURCE: DIGI P6.49KLCT-ND; TOLERANCE: 1%; Type: resistor; VPC: 1/16W; Vendor: Yageo
R632 R640 R642-R646 R660-R667 R859 = PAS,R,large: ALT_SYMBOLS: 0402_1mm; CCA: 63; DigiKey: 311-10.0KLRCT-ND; Family: passive; ICA_MFR_NAME: PANASONIC; ICA_PARTNUM: $$1785048$$ERJ-3GSYJ102; Index PN: 680; Install: Y; Lead Style: SMT; MFG: Yageo; Material: chip; P/D_NUM: RC0402FR-0710KL; Part Number: RC0402FR-0710KL; Power: 1/16W; TOLERANCE: 1%; Type: resistor; VPC: 1/16W; Vendor: Yageo
R860 = PAS,R,large: ALT_SYMBOLS: 0402_1mm; CCA: 65; DigiKey: 311-10.0KLRCT-ND; Family: passive; ICA_MFR_NAME: PANASONIC; ICA_PARTNUM: $$1785048$$ERJ-3GSYJ102; Index PN: 680; Install: Y; Lead Style: SMT; MFG: Yageo; Material: chip; P/D_NUM: RC0402FR-0710KL; Part Number: RC0402FR-0710KL; Power: 1/16W; TOLERANCE: 1%; Type: resistor; VPC: 1/16W; Vendor: Yageo
TP20 TP148-TP151 TP153-TP156 TP163-TP170 TP268-TP271 = EM,TERM,TESTPOINT: DigiKey: 36-5012-ND; Family: electro/mechanical; Index PN: 1162; Install: DNI; Lead Style: TH; MFG: Keystone; P/D_NUM: 5012; Part Number: 5012; Part Specific: TEST POINT PC MULTI PURPOSE WHT .063inD hole; Type: terminal; Vendor: Keystone
U43 U49 = LOG,BUF,74X827A: DigiKey: 296-8548-1-ND; Family: logic; Index PN: 1487; Lead Style: SMT; MFG: Texas Instruments; Part Specific: IC BUFF/DVR TRI-ST 10BIT 24TSSOP; Type: buffer; Vendor: Texas Instruments
U47 = LOG,BUF,74LVC1G125,1x: DigiKey: 296-11603-1-ND; Family: logic; Index PN: 1496; Lead Style: SMT; MFG: Texas Instruments; P/D_NUM: SN74LVC1G125DBVR; Part Number: SN74LVC1G125DBVR; Part Specific: IC BUS BUFF TRI-ST N-INV SOT23-5; Type: buffer; Vendor: Texas Instruments
U48 = TMP_31: DigiKey: 296-8483-1-ND; Family: logic; Index PN: 1489; Lead Style: SMT; MFG: Texas Instruments; Part Specific: IC INVERTER SGL 1INPUT Open Drain; Type: inverter

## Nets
GND: C1.2 C8.2 C34.2 C71.2 C74.2 C91.2 C95.2 C96.2 C97.2 C108.2 C109.2 C110.2 C124.2 C126.2 C127.2 C130.2 C138.1 C148.2 C149.2 C150.2 C152.1 C153.2 C154.2 C155.2 C156.2 C157.2 C158.2 C159.2 C160.2 C161.1 C162.2 C163.2 C164.2 C165.2 C166.2 C167.2 C168.2 C169.2 C170.1 C171.2 C172.1 C173.2 C174.2 C175.1 C176.2 C177.2 C178.2 C179.2 C180.2 C181.2 C182.2 C183.2 C184.2 C185.2 C186.2 C187.2 C188.2 C189.2 C190.2 C191.2 C192.2 C193.2 C194.2 C195.2 C196.2 C197.2 C198.2 C199.2 C200.2 C201.2 C202.1 C203.2 C204.2 C205.2 C206.2 C207.2 C208.2 C209.2 C210.1 C211.1 C212.2 C213.2 C214.2 C215.2 C216.1 C217.2 C218.2 C219.2 C220.2 C221.2 C222.2 C223.2 C224.2 C225.2 C226.2 C227.2 C228.2 C229.2 C230.2 C233.2 C234.2 C235.2 C236.2 C237.2 C238.2 C239.2 C240.1 C241.2 C242.2 C243.2 C244.2 C245.2 C246.2 C247.2 C248.2 C249.2 C250.2 C251.2 C252.2 C253.2 C254.2 C255.2 C256.2 C257.2 C258.2 C259.1 C260.2 C261.2 C262.2 C263.2 C264.2 C265.2 C266.2 C267.2 C268.2 C269.2 C275.2 C276.2 C277.2 C278.2 C279.2 C280.2 C281.2 C282.2 C283.2 C284.2 C285.2 C286.2 C287.2 C288.2 C289.2 C290.2 C291.2 C300.2 C301.2 C302.2 C303.2 C304.2 C317.2 C502.1 C507.1 C508.1 C557.1 C576.1 C583.2 C664.1 C675.1 C699.2 C830.1 J4.2 J5.2 J8.2 J28.3 J28.5 J28.7 J28.9 J28.11 J97.7 J97.10 J97.15 J97.16 J114.3 J115.1 Q6.2(SOURCE) R2.2(N2) R62.2(N2) R63.2(N2) R88.2(N2) R632.2(N2) R640.2(N2) R642.2(N2) R643.2(N2) R644.2(N2) R645.2(N2) R646.2(N2) R660.2(N2) R661.2(N2) R662.2(N2) R663.2(N2) R664.2(N2) R665.2(N2) R666.2(N2) R667.2(N2) R859.2(N2) R865.2(N2) TP1.1(P1) TP2.1(P1) TP11.1(P1) TP14.1(P1) TP38.1(P1) TP39.1(P1) U2.3(GND) U3.3(GND) U13.3(GND) U14.3(GND) U15.A1(VSS) U15.A2(VSS) U15.A3(VSS) U15.A5(VSS) U15.A7(VSS) U15.A9(VSS) U15.A11(VSS) U15.A13(VSS) U15.A15(VSS) U15.A18(VSS) U15.A20(VSS) U15.A22(VSS) U15.A24(VSS) U15.A26(VSS) U15.A28(VSS) U15.A30(VSS) U15.AA25(VSS) U15.AA28(VSS) U15.AB1(VSS) U15.AB6(VSS) U15.AB30(VSS) U15.AC3(VSS) U15.AC25(VSS) U15.AC27(VSS) U15.AD6(VSS) U15.AE1(VSS) U15.AE5(VSS) U15.AE7(VSS) U15.AE9(VSS) U15.AE11(VSS) U15.AE15(VSS) U15.AE17(VSS) U15.AE21(VSS) U15.AE23(VSS) U15.AE25(VSS) U15.AE26(VSS) U15.AE28(VSS) U15.AF3(VSS) U15.AF5(VSS) U15.AF6(VSS) U15.AF8(VSS) U15.AF10(VSS) U15.AF12(VSS) U15.AF14(VSS) U15.AF15(VSS) U15.AF17(VSS) U15.AF18(VSS) U15.AF19(VSS) U15.AF20(VSS) U15.AF22(VSS) U15.AF24(VSS) U15.AF26(VSS) U15.AF28(VSS) U15.AF30(VSS) U15.AG4(VSS) U15.AG6(VSS) U15.AG8(VSS) U15.AG10(VSS) U15.AG12(VSS) U15.AG14(VSS) U15.AG16(VSS) U15.AG18(VSS) U15.AG23(VSS) U15.AG25(VSS) U15.AG27(VSS) U15.AG29(VSS) U15.AH1(VSS) U15.AH2(VSS) U15.AH3(VSS) U15.AH4(VSS) U15.AH6(VSS) U15.AH8(VSS) U15.AH10(VSS) U15.AH12(VSS) U15.AH14(VSS) U15.AH16(VSS) U15.AH18(VSS) U15.AH21(VSS) U15.AH23(VSS) U15.AH25(VSS) U15.AH27(VSS) U15.AH29(VSS) U15.AH30(VSS) U15.AJ1(VSS) U15.AJ3(VSS) U15.AJ5(VSS) U15.AJ7(VSS) U15.AJ9(VSS) U15.AJ11(VSS) U15.AJ13(VSS) U15.AJ15(VSS) U15.AJ17(VSS) U15.AJ22(VSS) U15.AJ24(VSS) U15.AJ26(VSS) U15.AJ28(VSS) U15.AJ30(VSS) U15.AK1(VSS) U15.AK3(VSS) U15.AK5(VSS) U15.AK7(VSS) U15.AK9(VSS) U15.AK11(VSS) U15.AK13(VSS) U15.AK15(VSS) U15.AK17(VSS) U15.AK22(VSS) U15.AK24(VSS) U15.AK26(VSS) U15.AK28(VSS) U15.AK30(VSS) U15.B1(VSS) U15.B2(VSS) U15.B3(VSS) U15.B5(VSS) U15.B7(VSS) U15.B9(VSS) U15.B11(VSS) U15.B13(VSS) U15.B18(VSS) U15.B20(VSS) U15.B22(VSS) U15.B24(VSS) U15.B26(VSS) U15.B28(VSS) U15.B30(VSS) U15.C3(VSS) U15.C4(VSS) U15.C6(VSS) U15.C8(VSS) U15.C10(VSS) U15.C12(VSS) U15.C14(VSS) U15.C17(VSS) U15.C19(VSS) U15.C21(VSS) U15.C23(VSS) U15.C25(VSS) U15.C29(VSS) U15.D1(VSS) U15.D2(VSS) U15.D6(VSS) U15.D8(VSS) U15.D10(VSS) U15.D12(VSS) U15.D14(VSS) U15.D17(VSS) U15.D19(VSS) U15.D21(VSS) U15.D23(VSS) U15.D25(VSS) U15.D28(VSS) U15.E3(VSS) U15.E4(VSS) U15.E5(VSS) U15.E7(VSS) U15.E9(VSS) U15.E11(VSS) U15.E13(VSS) U15.E15(VSS) U15.E22(VSS) U15.E25(VSS) U15.E28(VSS) U15.F1(VSS) U15.F2(VSS) U15.F5(VSS) U15.F6(VSS) U15.F8(VSS) U15.F10(VSS) U15.F12(VSS) U15.F13(VSS) U15.F17(VSS) U15.F18(VSS) U15.F20(VSS) U15.F30(VSS) U15.G3(VSS) U15.G4(VSS) U15.G5(VSS) U15.G25(VPGM) U15.G27(VSS) U15.H1(VSS) U15.H2(VSS) U15.H5(VSS) U15.H6(VSS) U15.J3(VSS) U15.J4(VSS) U15.J5(VSS) U15.J25(VSS) U15.J28(VSS) U15.K6(VSS) U15.K30(VSS) U15.L1(VSS) U15.L25(VSS) U15.L27(VSS) U15.M3(VSS) U15.M6(VSS) U15.M12(VSS) U15.M13(VSS) U15.M14(VSS) U15.M15(VSS) U15.M16(VSS) U15.M17(VSS) U15.M18(VSS) U15.M19(VSS) U15.N1(VSS) U15.N12(VSS) U15.N13(VSS) U15.N14(VSS) U15.N15(VSS) U15.N16(VSS) U15.N17(VSS) U15.N18(VSS) U15.N19(VSS) U15.N25(VSS) U15.N28(VSS) U15.P6(VSS) U15.P12(VSS) U15.P13(VSS) U15.P14(VSS) U15.P15(VSS) U15.P16(VSS) U15.P17(VSS) U15.P18(VSS) U15.P19(VSS) U15.P30(VSS) U15.R3(VSS) U15.R12(VSS) U15.R13(VSS) U15.R14(VSS) U15.R15(VSS) U15.R16(VSS) U15.R17(VSS) U15.R18(VSS) U15.R19(VSS) U15.R25(VSS) U15.R27(VSS) U15.T1(VSS) U15.T6(VSS) U15.T12(VSS) U15.T13(VSS) U15.T14(VSS) U15.T15(VSS) U15.T16(VSS) U15.T17(VSS) U15.T18(VSS) U15.T19(VSS) U15.U3(VSS) U15.U5(VSS) U15.U12(VSS) U15.U13(VSS) U15.U14(VSS) U15.U15(VSS) U15.U16(VSS) U15.U17(VSS) U15.U18(VSS) U15.U19(VSS) U15.U25(VSS) U15.U28(VSS) U15.V6(VSS) U15.V12(VSS) U15.V13(VSS) U15.V14(VSS) U15.V15(VSS) U15.V16(VSS) U15.V17(VSS) U15.V18(VSS) U15.V19(VSS) U15.V30(VSS) U15.W1(VSS) U15.W5(VSS) U15.W12(VSS) U15.W13(VSS) U15.W14(VSS) U15.W15(VSS) U15.W16(VSS) U15.W17(VSS) U15.W18(VSS) U15.W19(VSS) U15.W25(VSS) U15.W27(VSS) U15.Y3(VSS) U15.Y6(VSS) U18.3(GND) U19.3(GND) U20.3(GND) U32.7(PGND) U32.8(PGND) U32.10(NC1) U32.13(AGND) U32.16(NC2) U32.18(PGND) U32.21(PAD) U33.3(GND) U43.1(~{OE1}) U43.12(GND) U43.13(~{OE2}) U47.1(~{OE}) U47.3(GND) U48.3(GND) U49.1(~{OE1}) U49.12(GND) U49.13(~{OE2}) U565.3(GND) ; also on sheet 3 4 5 6 7 8 9 10 11 12 15 16 17 18 19 20 26
P5V: C507.2 J28.1 ; also on sheet 3 10 15
P12V: C1.1 C8.1 C71.1 C124.1 C130.1 C830.2 J4.1 J5.1 J8.1 J97.2 J114.1 U32.2(VIN) U32.3(VIN) U32.4(VIN) U32.5(VIN) ; also on sheet 7 12 17
VDD33_FPD: C170.2 C230.1 C255.1 C258.1 C265.1 C266.1 C267.1 C287.1 C288.1 C289.1 L506.2 U15.E6(VDD33_FPD) U15.E8(VDD33_FPD) U15.E10(VDD33_FPD) U15.E12(VDD33_FPD) U15.E14(VDD33_FPD) U15.G6(VDD33_FPD) U15.L11(VDD33_FPD) U15.L13(VDD33_FPD)
VDD115_FPD: C257.1 C259.2 C262.1 C263.1 C264.1 C284.1 C286.1 L505.1 U15.F7(VDD115_FPD) U15.F9(VDD115_FPD) U15.F11(VDD115_FPD) U15.J6(VDD115_FPD) U15.L12(VDD115_FPD)
VDD115_HSSI0_PLL: C155.1 C159.1 L13.1 U15.AE22(VDD115_HSSI0_PLL)
VDD115_HSSI1_PLL: C236.1 C239.1 L24.1 U15.AE10(VDD115_HSSI1_PLL)
VDD115_PLLMA: C180.1 C182.1 L16.1 U15.AE18(VDD115_PLLMA)
VDD115_PLLMB: C224.1 C228.1 L22.1 U15.F15(VDD115_PLLMB)
VDD115_PLLS: C226.1 C229.1 L21.1 U15.F16(VDD115_PLLS)
DMD_OK: R87.2(N2) U3.1(A)
DYN_BLK: J86.2 R859.1(N1) U47.2(I)
DYN_BLK_1: R259.2(N2) U47.4(O)
DYN_BLK_2: J114.2 R259.1(N1)
FE_PROJ_ON: R88.1(N1) U565.1(A) ; also on sheet 15
LD_SPOKE_OFFZ: R667.1(N1) TP167.1(P1) U49.8(A7)
LD_SPOKE_OFFZ_OUT: J97.18 J115.2 U49.17(Y7)
LED_EN: J106.2 J115.3
LED_EN_BLU: J97.8 J115.8 U49.21(Y3)
LED_EN_GRN: J97.6 J115.7 U49.22(Y2)
LED_EN_IR: J97.22 U49.20(Y4)
LED_EN_RED: J97.4 J115.6 U49.23(Y1)
LED_EN_UV: J97.20 U49.19(Y5)
LEDSEL_0: R666.1(N1) U49.2(A1) ; also on sheet 20
LEDSEL_1: R665.1(N1) U49.3(A2) ; also on sheet 20
LEDSEL_2: R664.1(N1) U49.4(A3) ; also on sheet 6 20
LEDSEL_3: R663.1(N1) U49.5(A4) ; also on sheet 20
LEDSEL_4: R662.1(N1) U49.6(A5) ; also on sheet 20
LMPCTRL: R660.1(N1) U49.10(A9) ; also on sheet 6 20
LMPCTRL_B: J106.3 U48.2(A) U49.15(Y9)
LMPCTRL_Bz: J106.1 R860.1(N1) U48.4(Y)
LMPSYNC: U49.9(A8) ; also on sheet 20
MSP_PROJ_ON: R865.1(N1) U565.2(B) ; also on sheet 5
P1P8V: C74.1 C95.1 C148.1 C165.1 C190.1 C201.1 C202.2 C207.1 C208.1 C210.2 C211.2 C212.1 C216.2 C220.1 C240.2 C241.1 C252.1 C261.1 C279.1 C281.1 C282.1 C291.1 C301.1 C303.1 L15.2 L19.2 L23.2 U15.AE13(VAD18_LSIF) U15.AE14(VAD18_LSIF) U15.AE16(VDD18_SCS) U15.L16(VDD18_SCS) U15.R6(VDD18_SCS) U15.T25(VDD18_SCS) U15.Y15(VAD18_LSIF) ; also on sheet 7 10 20
P1P15V: C34.1 C96.1 C108.1 C109.1 C110.1 C127.1 C149.1 C154.1 C156.1 C161.2 C167.1 C178.1 C186.1 C188.1 C191.1 C193.1 C195.1 C199.1 C203.1 C209.1 C213.1 C214.1 C217.1 C218.1 C222.1 C223.1 C233.1 C234.1 C235.1 C243.1 C246.1 C249.1 C250.1 C253.1 C256.1 C300.1 C302.1 C304.1 C576.2 C583.1 L11.2 L13.2 L16.2 L18.2 L21.2 L22.2 L24.2 L505.2 R64.1(N1) R65.2(N2) R66.2(N2) U15.AF7(VDD115_HSSI) U15.AF9(VDD115_HSSI) U15.AF11(VDD115_HSSI) U15.AF13(VDD115_HSSI) U15.AF21(VDD115_HSSI) U15.AF23(VDD115_HSSI) U15.AF25(VDD115_HSSI) U15.L14(VDD115) U15.L20(VDD115) U15.M11(VDD115) U15.N20(VDD115) U15.P11(VDD115) U15.R20(VDD115) U15.T11(VDD115) U15.U20(VDD115) U15.V11(VDD115) U15.W20(VDD115) U15.Y11(VDD115) U15.Y13(VDD115) U15.Y14(VDD115_HSSI) U15.Y17(VDD115) U15.Y19(VDD115_HSSI)
P1P15V_BST: C125.1 U32.1(BST)
P1P15V_DRAIN: Q6.1(GATE) R76.1(N1) R77.2(N2)
P1P15V_DRAIN_BUF: R77.1(N1) U33.4(Y)
P1P15V_EN: U32.12(EN) U33.2(A) ; also on sheet 7
P1P15V_FB: R62.1(N1) R64.2(N2) U32.14(FB)
P1P15V_FET: Q6.3(DRAIN) R65.1(N1) R66.1(N1)
P1P15V_MODE: R61.2(N2) R63.1(N1) U32.15(MODE)
P1P15V_PG: R75.2(N2) U32.9(PGD) ; also on sheet 7
P1P15V_SS: C317.1 U32.11(SS)
P1P15V_SW: C125.2 L11.1 U32.6(SW) U32.19(SW) U32.20(SW)
P1P15V_VCC: C126.1 R61.1(N1) U32.17(VCC)
P1P21V: C91.1 C164.1 C184.1 C189.1 C194.1 C215.1 C221.1 C247.1 C248.1 C254.1 C260.1 C269.1 U15.L15(VDD12_SCS) U15.N11(VDD12_SCS) U15.P20(VDD12_SCS) U15.U11(VDD12_SCS) U15.V20(VDD12_SCS) U15.Y16(VDD12_SCS) ; also on sheet 7 10
P3P3V: C97.1 C150.1 C153.1 C157.1 C158.1 C160.1 C162.1 C163.1 C166.1 C168.1 C169.1 C171.1 C173.1 C176.1 C177.1 C181.1 C185.1 C192.1 C196.1 C206.1 C237.1 C238.1 C242.1 C244.1 C245.1 C251.1 C268.1 C275.1 C276.1 C277.1 C278.1 C280.1 C283.1 C285.1 C290.1 C502.2 C508.2 C557.2 C664.2 C675.2 C699.1 J28.12 L14.2 L17.2 L20.2 L506.1 R121.1(N1) R125.1(N1) R860.2(N2) U15.AA6(VDD33) U15.AB25(VDD33) U15.AC6(VDD33) U15.AD25(VDD33) U15.AE6(VDD33) U15.AE8(VDD33_HSSI) U15.AE12(VDD33_HSSI) U15.AE20(VDD33_HSSI) U15.AE24(VDD33_HSSI) U15.H25(VDD33) U15.K25(VDD33) U15.L6(VDD33) U15.M20(VDD33) U15.M25(VDD33) U15.N6(VDD33) U15.P25(VDD33) U15.R11(VDD33) U15.T20(VDD33) U15.U6(VDD33) U15.V25(VDD33) U15.W6(VDD33) U15.W11(VDD33) U15.Y12(VDD33_HSSI) U15.Y20(VDD33_HSSI) U15.Y25(VDD33) U43.24(VCC) U47.5(VCC) U48.5(PWR) U49.24(VCC) ; also on sheet 4 6 7 8 9 10 11 12 15 16 18 19 20 26
P3P3V_SB: D5.2(ANODE) D7.2(ANODE) D8.2(ANODE) R1.2(N2) R75.1(N1) R76.2(N2) R87.1(N1) R153.1(N1) U2.5(VCC) U3.5(VCC) U13.5(PWR) U14.5(PWR) U18.5(PWR) U19.5(PWR) U20.5(PWR) U33.5(PWR) U565.5(VCC) ; also on sheet 4 5 7 19
PMIC_PWRGOOD: R153.2(N2) U13.2(A) U14.2(A) ; also on sheet 7 8 9 10
POSENSE: U20.2(A) ; also on sheet 8 9 10 16 18
POSENSE_DRVZ: R43.2(N2) U20.4(Y)
POSENSE_LED: D8.1(CATHODE) R43.1(N1)
PROJ_ON: U3.4(Y) U18.2(A) U19.2(A) ; also on sheet 7
PROJ_ON_1: U2.1(A) U565.4(Y)
PROJ_ON_3: U2.4(Y) U3.2(B)
PROJ_ON_DRV: R42.2(N2) U19.4(Y)
PROJ_ON_LED: D7.1(CATHODE) R42.1(N1)
PROJ_ON_OD: R125.2(N2) U18.4(Y) ; also on sheet 20
PWM_BLU: J97.5 U43.21(Y3)
PWM_GRN: J97.3 U43.22(Y2)
PWM_IR: J97.9 U43.20(Y4)
PWM_OUT_BLED: R643.1(N1) U43.4(A3) ; also on sheet 20
PWM_OUT_GLED: R644.1(N1) U43.3(A2) ; also on sheet 20
PWM_OUT_IRLED: R642.1(N1) U43.5(A4) ; also on sheet 20
PWM_OUT_RLED: R645.1(N1) U43.2(A1) ; also on sheet 20
PWM_OUT_STD_0: J86.1 R640.1(N1) U43.7(A6) ; also on sheet 20
PWM_OUT_STD_1: J86.3 R632.1(N1) U43.8(A7) ; also on sheet 20
PWM_RED: J97.1 U43.23(Y1)
PWM_STD_0: J97.13 U43.18(Y6)
PWM_STD_1: J97.17 U43.17(Y7)
PWRGOOD: R121.2(N2) U13.4(Y) ; also on sheet 18
PWRGOOD_DRV: R37.2(N2) U14.4(Y)
PWRGOOD_LED: D5.1(CATHODE) R37.1(N1)
SAS_CLK: J28.4 TP20.1(P1) ; also on sheet 20
SAS_CSZ: J28.10 TP271.1(P1) ; also on sheet 20
SAS_DI: J28.6 TP270.1(P1) ; also on sheet 20
SAS_DO: J28.8 TP268.1(P1) ; also on sheet 20
SAS_INTGTR_EN: J28.2 TP269.1(P1) ; also on sheet 19 20
SENSE_PULSE_OUT: J97.12 J115.12 U49.16(Y8)
SPARE_J39_4: J115.4 TP164.1(P1)
SPARE_J39_9: J115.9 TP165.1(P1)
SPARE_J39_10: J115.10 TP166.1(P1)
SPARE_J39_11: J115.11 TP168.1(P1)
SPARE_J202_14: J97.14 TP153.1(P1)
spare_U32_18: J115.5 U49.18(Y6)
SPARE_U39_6: TP155.1(P1) U43.6(A5)
SPARE_U39_10: TP150.1(P1) U43.9(A8)
SPARE_U39_11: TP151.1(P1) U43.10(A9)
SPARE_U39_12: TP156.1(P1) U43.11(A10)
SPARE_U39_14: TP149.1(P1) U43.14(Y10)
SPARE_U39_15: TP154.1(P1) U43.15(Y9)
SPARE_U39_16: J97.19 U43.16(Y8)
SPARE_U39_19: J97.11 U43.19(Y5)
SPARE_U508_7: R661.1(N1) TP170.1(P1) U49.7(A6)
SPARE_U508_11: R646.1(N1) TP169.1(P1) U49.11(A10)
SPARE_U508_14: TP163.1(P1) U49.14(Y10)
SUBFRAME: J97.21 TP148.1(P1)
SW_PROJ_ON: C138.2 SW1.2 U2.2(B) ; also on sheet 4
SW_PROJ_ON_PD: R2.1(N1) SW1.1 SW1.4
SW_PROJ_ON_PU: R1.1(N1) SW1.3 SW1.6
VAD18_PLLMA: C179.1 C183.1 L15.1 U15.AE19(VAD18_PLLMA)
VAD18_PLLMB: C225.1 C227.1 L23.1 U15.F14(VAD18_PLLMB)
VAD18_VX1: C197.1 C204.1 C205.1 L19.1 U15.E18(VAD18_VX1) U15.L19(VAD18_VX1)
VAD33_OSCA: C187.1 L17.1 U15.Y18(VAD33_OSCA)
VAD33_OSCB: C219.1 L20.1 U15.L17(VAD33_OSCB)
VAD33_USB: C152.2 C172.2 C175.2 L14.1 U15.D27(VAD33_USB) U15.E26(VAD33_USB) U15.F25(VAD33_USB)
VAD115_VX1: C174.1 C198.1 C200.1 L18.1 U15.F24(VAD115_VX1) U15.L18(VAD115_VX1)
Vx1_CM_AMOUT0: TP106.1(P1) U15.F19(VX1_CM_AMOUT0)
Vx1_CM_AMOUT1: TP107.1(P1) U15.F21(VX1_CM_AMOUT1)
Vx1_CM_AMOUT2: TP108.1(P1) U15.F22(VX1_CM_AMOUT2)
Vx1_CM_AMOUT3: TP109.1(P1) U15.F23(VX1_CM_AMOUT3)

Not connected (* = marked no-connect by the designer): U13 1*; U14 1*; U18 1*; U19 1*; U20 1*; U33 1*; U48 1*

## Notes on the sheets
sheet 21
- PROJ_ON can be driven
  from Front End card or
  on-board Switch.
- DO NOT DRIVE DLPC7540 PIN
  HIGH BEFORE P3P3V IS ON.
- Rev E.2 Mod
- DO NOT DRIVE DLPC7540 PIN
  HIGH BEFORE P3P3V IS ON.
- 1.15V/10A
- Power for DLPC
  Heat Sink Fan
- DLPC7540 Core Power & PROJ_ON Control
- (C) COPYRIGHT 2020
         Texas Instruments
        All Rights Reserved
sheet 22
- (C) COPYRIGHT 2020
  Texas Instruments
  All Rights Reserved
sheet 23
- DLPC GND & No Connects
- (C) COPYRIGHT 2020
         Texas Instruments
        All Rights Reserved
sheet 24
- (C) COPYRIGHT 2020
         Texas Instruments
        All Rights Reserved
sheet 25
- ADC INTEGRATING SENSOR BOARD I/F
- DYNAMIC BLACK I/F
- {CIPO}
- {COPI}
- {G_LED_EN}
- {R_LED_EN}
- {B_LED_EN}
- {IR_LED_EN}
- {UV_LED_EN}
- {LAMP SYNC/LED SENSE}
- (C) COPYRIGHT 2020
         Texas Instruments
        All Rights Reserved
